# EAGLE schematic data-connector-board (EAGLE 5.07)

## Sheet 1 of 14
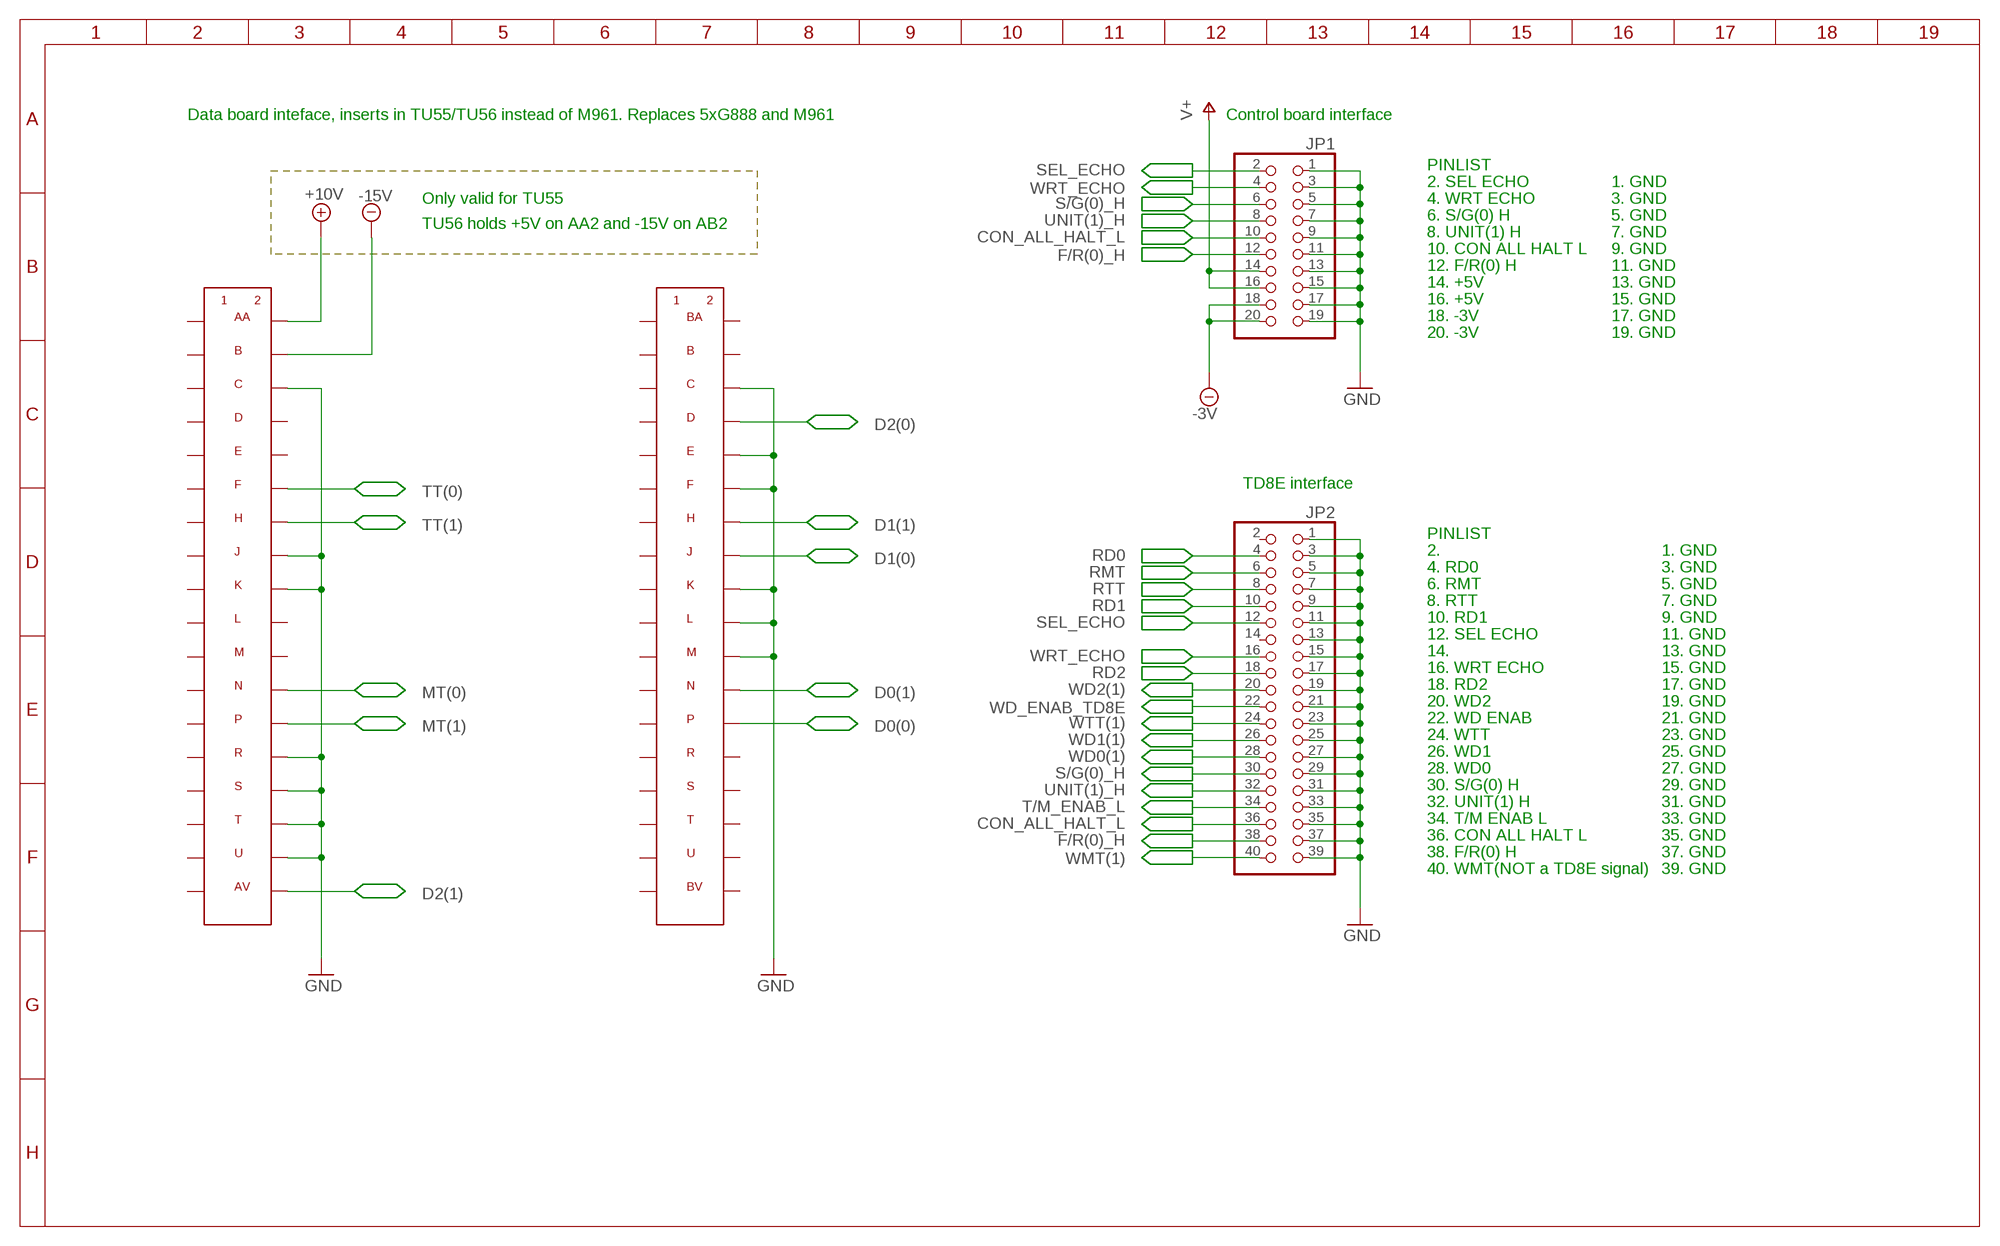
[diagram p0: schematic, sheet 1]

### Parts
J1  FLIPCHIP_2  FLIPCHIP_2-SBSOPEN  [FLIPCHIP-2-OPEN]
JP1  PINHD-2X10/90-FRAMED  [2Z10/90-FRAMED]
JP2  PINHD-2X20/90-FRAMED  [2X20/90-FRAMED]

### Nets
+10V: J1.AA2 ; also sheet 13
-3V: JP1.18 JP1.20 ; also sheet 13,14
-15V: J1.AB2 ; also sheet 13
CON_ALL_HALT_L: JP1.10 JP2.36
D0(0): J1.BP2 ; also sheet 4,9
D0(1): J1.BN2 ; also sheet 4,9
D1(0): J1.BJ2 ; also sheet 5,10
D1(1): J1.BH2 ; also sheet 5,10
D2(0): J1.BD2 ; also sheet 6,11
D2(1): J1.AV2 ; also sheet 6,11
F/R(0)_H: JP1.12 JP2.38
GND: J1.AC2 J1.AJ2 J1.AK2 J1.AR2 J1.AS2 J1.AT2 J1.AU2 J1.BC2 J1.BE2 J1.BF2 J1.BK2 J1.BL2 J1.BM2 JP1.1 JP1.3 JP1.5 JP1.7 JP1.9 JP1.11 JP1.13 JP1.15 JP1.17 JP1.19 JP2.1 JP2.3 JP2.5 JP2.7 JP2.9 JP2.11 JP2.13 JP2.15 JP2.17 JP2.19 JP2.21 JP2.23 JP2.25 JP2.27 JP2.29 JP2.31 JP2.33 JP2.35 JP2.37 JP2.39 ; also sheet 2,3,4,5,6,7,8,9,10,11,12,13
MT(0): J1.AN2 ; also sheet 3,8
MT(1): J1.AP2 ; also sheet 3,8
RD0: JP2.4 ; also sheet 4,14
RD1: JP2.10 ; also sheet 5,14
RD2: JP2.18 ; also sheet 6,14
RMT: JP2.6 ; also sheet 3,14
RTT: JP2.8 ; also sheet 2,14
S/G(0)_H: JP1.6 JP2.30
SEL_ECHO: JP1.2 JP2.12
T/M_ENAB_L: JP2.34 ; also sheet 12
TT(0): J1.AF2 ; also sheet 2,7
TT(1): J1.AH2 ; also sheet 2,7
UNIT(1)_H: JP1.8 JP2.32
V+: JP1.14 JP1.16 ; also sheet 2,3,4,5,6,7,8,9,10,11,12,13,14
WD0(1): JP2.28 ; also sheet 8,9
WD1(1): JP2.26 ; also sheet 10
WD2(1): JP2.20 ; also sheet 11
WD_ENAB_TD8E: JP2.22 ; also sheet 12
WMT(1): JP2.40 ; also sheet 8
WRT_ECHO: JP1.4 JP2.16
WTT(1): JP2.24 ; also sheet 7
Unconnected: J1.AA1 J1.AB1 J1.AC1 J1.AD1 J1.AD2 J1.AE1 J1.AE2 J1.AF1 J1.AH1 J1.AJ1 J1.AK1 J1.AL1 J1.AL2 J1.AM1 J1.AM2 J1.AN1 J1.AP1 J1.AR1 J1.AS1 J1.AT1 J1.AU1 J1.AV1 J1.BA1 J1.BA2 J1.BB1 J1.BB2 J1.BC1 J1.BD1 J1.BE1 J1.BF1 J1.BH1 J1.BJ1 J1.BK1 J1.BL1 J1.BM1 J1.BN1 J1.BP1 J1.BR1 J1.BR2 J1.BS1 J1.BS2 J1.BT1 J1.BT2 J1.BU1 J1.BU2 J1.BV1 J1.BV2 JP2.2 JP2.14

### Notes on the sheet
- Data board inteface, inserts in TU55/TU56 instead of M961. Replaces 5xG888 and M961 | Control board interface
- PINLIST
- 2. SEL ECHO | 1. GND
- Only valid for TU55 | 4. WRT ECHO | 3. GND
- 6. S/G(0) H | 5. GND
- TU56 holds +5V on AA2 and -15V on AB2
- 8. UNIT(1) H | 7. GND
- 10. CON ALL HALT L | 9. GND
- 12. F/R(0) H | 11. GND
- 14. +5V | 13. GND
- 16. +5V | 15. GND
- 18. -3V | 17. GND
- 20. -3V | 19. GND
- TD8E interface
- PINLIST
- 2. | 1. GND
- 4. RD0 | 3. GND
- 6. RMT | 5. GND
- 8. RTT | 7. GND
- 10. RD1 | 9. GND
- 12. SEL ECHO | 11. GND
- 14. | 13. GND
- 16. WRT ECHO | 15. GND
- 18. RD2 | 17. GND
- 20. WD2 | 19. GND
- 22. WD ENAB | 21. GND
- 24. WTT | 23. GND
- 26. WD1 | 25. GND
- 28. WD0 | 27. GND
- 30. S/G(0) H | 29. GND
- 32. UNIT(1) H | 31. GND
- 34. T/M ENAB L | 33. GND
- 36. CON ALL HALT L | 35. GND
- 38. F/R(0) H | 37. GND
- 40. WMT(NOT a TD8E signal) | 39. GND

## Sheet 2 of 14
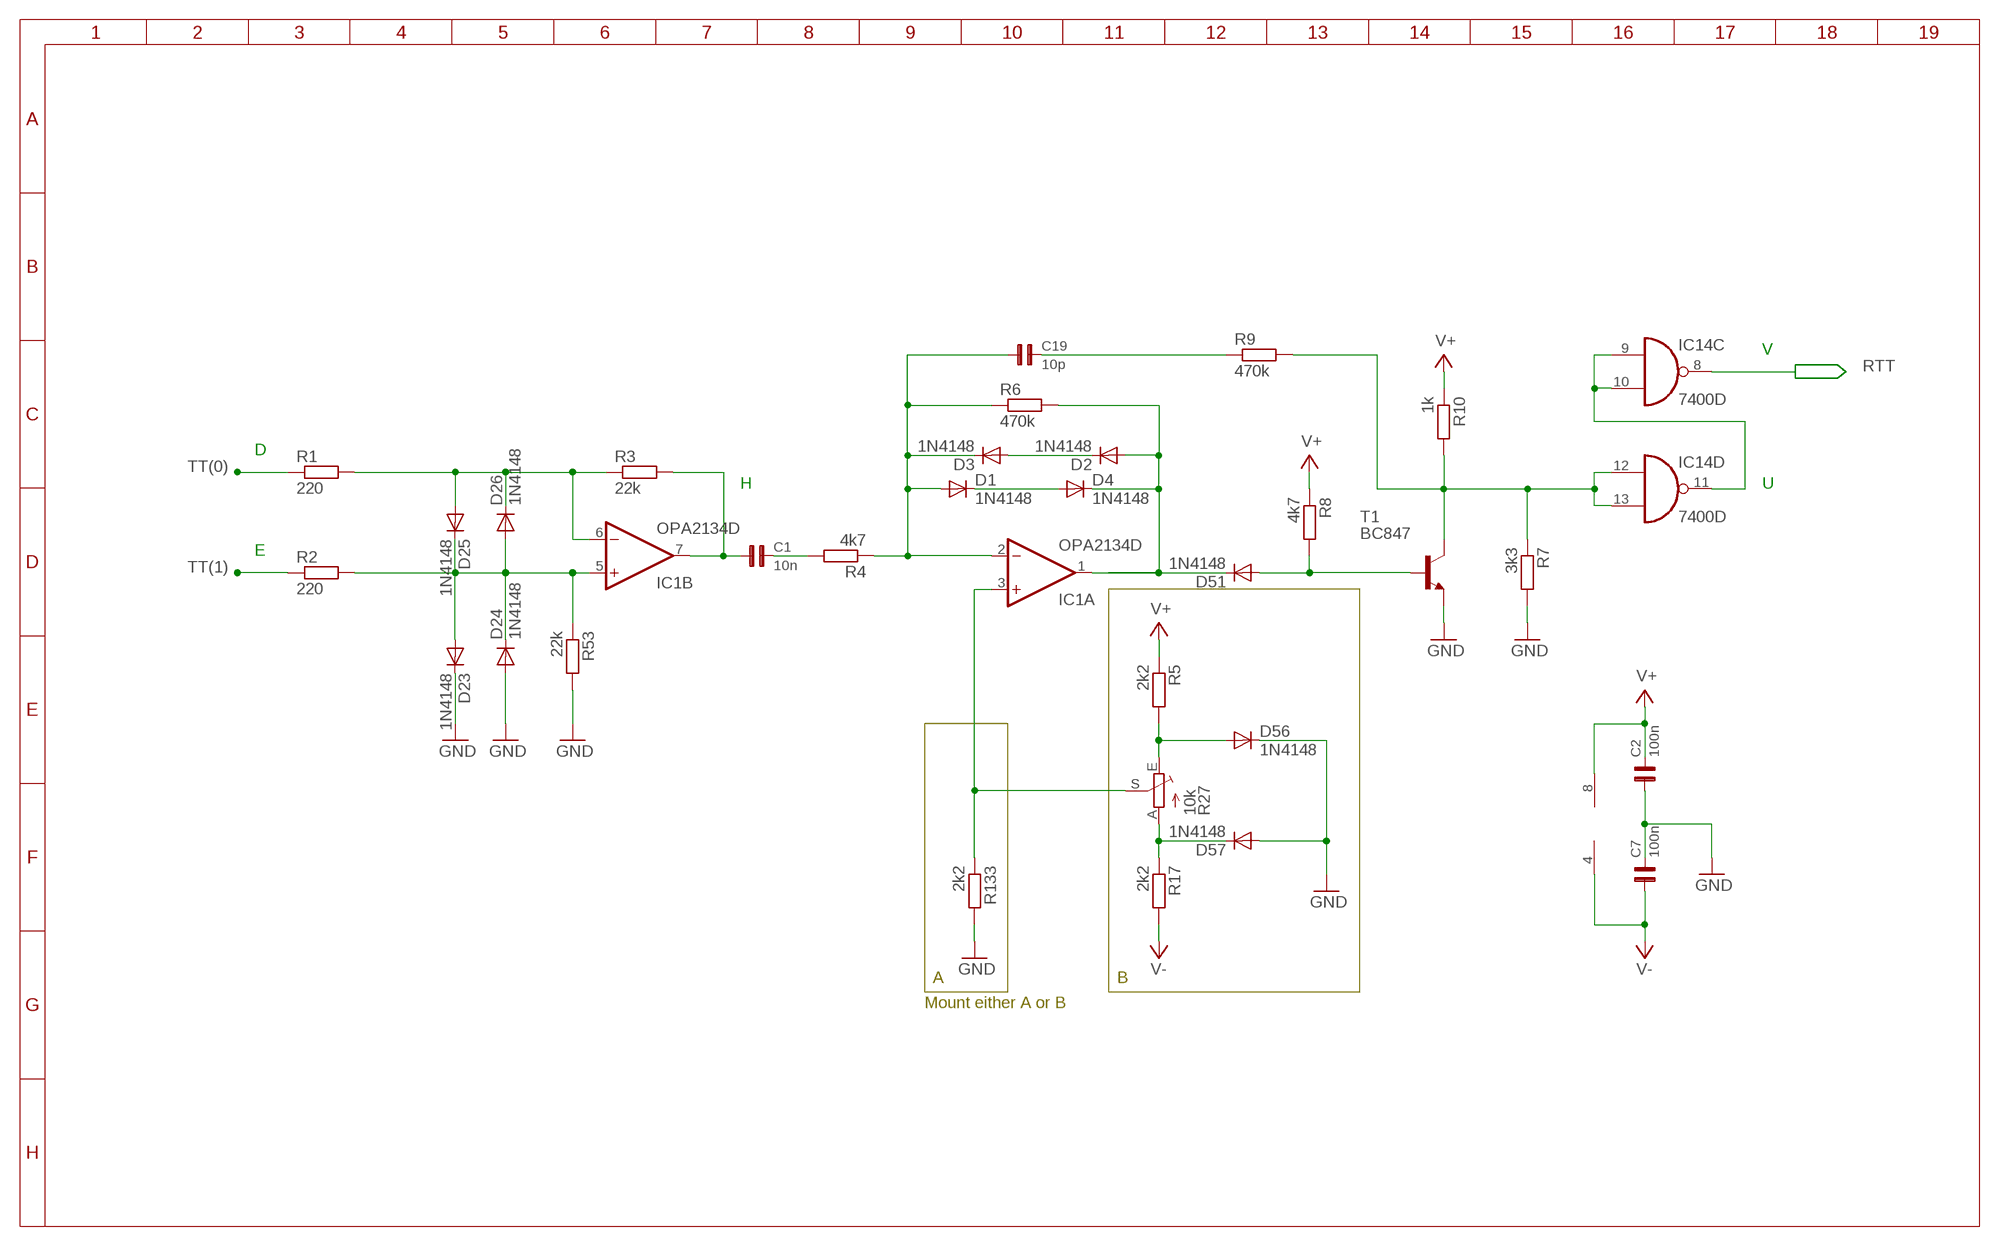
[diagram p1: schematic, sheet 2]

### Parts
C1  10n  C0805  [0805]
C2  100n  C0805  [0805]
C7  100n  C0805  [0805]
C19  10p  C0805  [0805]
D1  1N4148  1N4148-Y  [SOD123]
D2  1N4148  1N4148-Y  [SOD123]
D3  1N4148  1N4148-Y  [SOD123]
D4  1N4148  1N4148-Y  [SOD123]
D23  1N4148  1N4148-Y  [SOD123]
D24  1N4148  1N4148-Y  [SOD123]
D25  1N4148  1N4148-Y  [SOD123]
D26  1N4148  1N4148-Y  [SOD123]
D51  1N4148  1N4148-Y  [SOD123]
D56  1N4148  1N4148-Y  [SOD123]
D57  1N4148  1N4148-Y  [SOD123]
IC1  OPA2134D  [SOIC8]
IC14  7400D  [SO14]
R1  220  R-EU_R0805  [R0805]
R2  220  R-EU_R0805  [R0805]
R3  22k  R-EU_R0805  [R0805]
R4  4k7  R-EU_R0805  [R0805]
R5  2k2  R-EU_R0805  [R0805]
R6  470k  R-EU_R0805  [R0805]
R7  3k3  R-EU_R0805  [R0805]
R8  4k7  R-EU_R0805  [R0805]
R9  470k  R-EU_R0805  [R0805]
R10  1k  R-EU_R0805  [R0805]
R17  2k2  R-EU_R0805  [R0805]
R27  10k  TRIM_EU-SP19L  [SP19L]
R53  22k  R-EU_R0805  [R0805]
R133  2k2  R-EU_R0805  [R0805]
T1  BC847  [SOT23]

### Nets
GND: C2.1 C7.2 D23.C D24.A D56.C D57.A R7.2 R53.2 R133.2 T1.2(E) ; also sheet 1,3,4,5,6,7,8,9,10,11,12,13
N$1: D25.A D26.C IC1.6(B:-IN) R1.2 R3.1
N$3: C1.1 IC1.7(B:OUT) R3.2
N$4: D1.C D4.A
N$5: C19.1 D1.A D3.C IC1.2(A:-IN) R4.1 R6.1
N$7: D2.A D4.C D51.C IC1.1(A:OUT) R6.2
N$8: D51.A R8.2 T1.1(B)
N$9: C19.2 R9.1
N$11: D2.C D3.A
N$12: C1.2 R4.2
N$33: IC1.3(A:+IN) R27.S R133.1
N$47: D56.A R5.2 R27.E
N$73: D57.C R17.1 R27.A
N$116: IC14.9(C:I0) IC14.10(C:I1) IC14.11(D:O)
N$128: D23.A D24.C D25.C D26.A IC1.5(B:+IN) R2.2 R53.1
RTT: IC14.8(C:O) ; also sheet 1,14
TIMING: IC14.12(D:I0) IC14.13(D:I1) R7.1 R9.2 R10.2 T1.3(C)
TT(0): R1.1 ; also sheet 1,7
TT(1): R2.1 ; also sheet 1,7
V+: C2.2 IC1.8(P:V+) R5.1 R8.1 R10.1 ; also sheet 1,3,4,5,6,7,8,9,10,11,12,13,14
V-: C7.1 IC1.4(P:V-) R17.2 ; also sheet 3,4,5,6,13,14

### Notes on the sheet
- V
- D
- H | U
- E
- A | B
- Mount either A or B

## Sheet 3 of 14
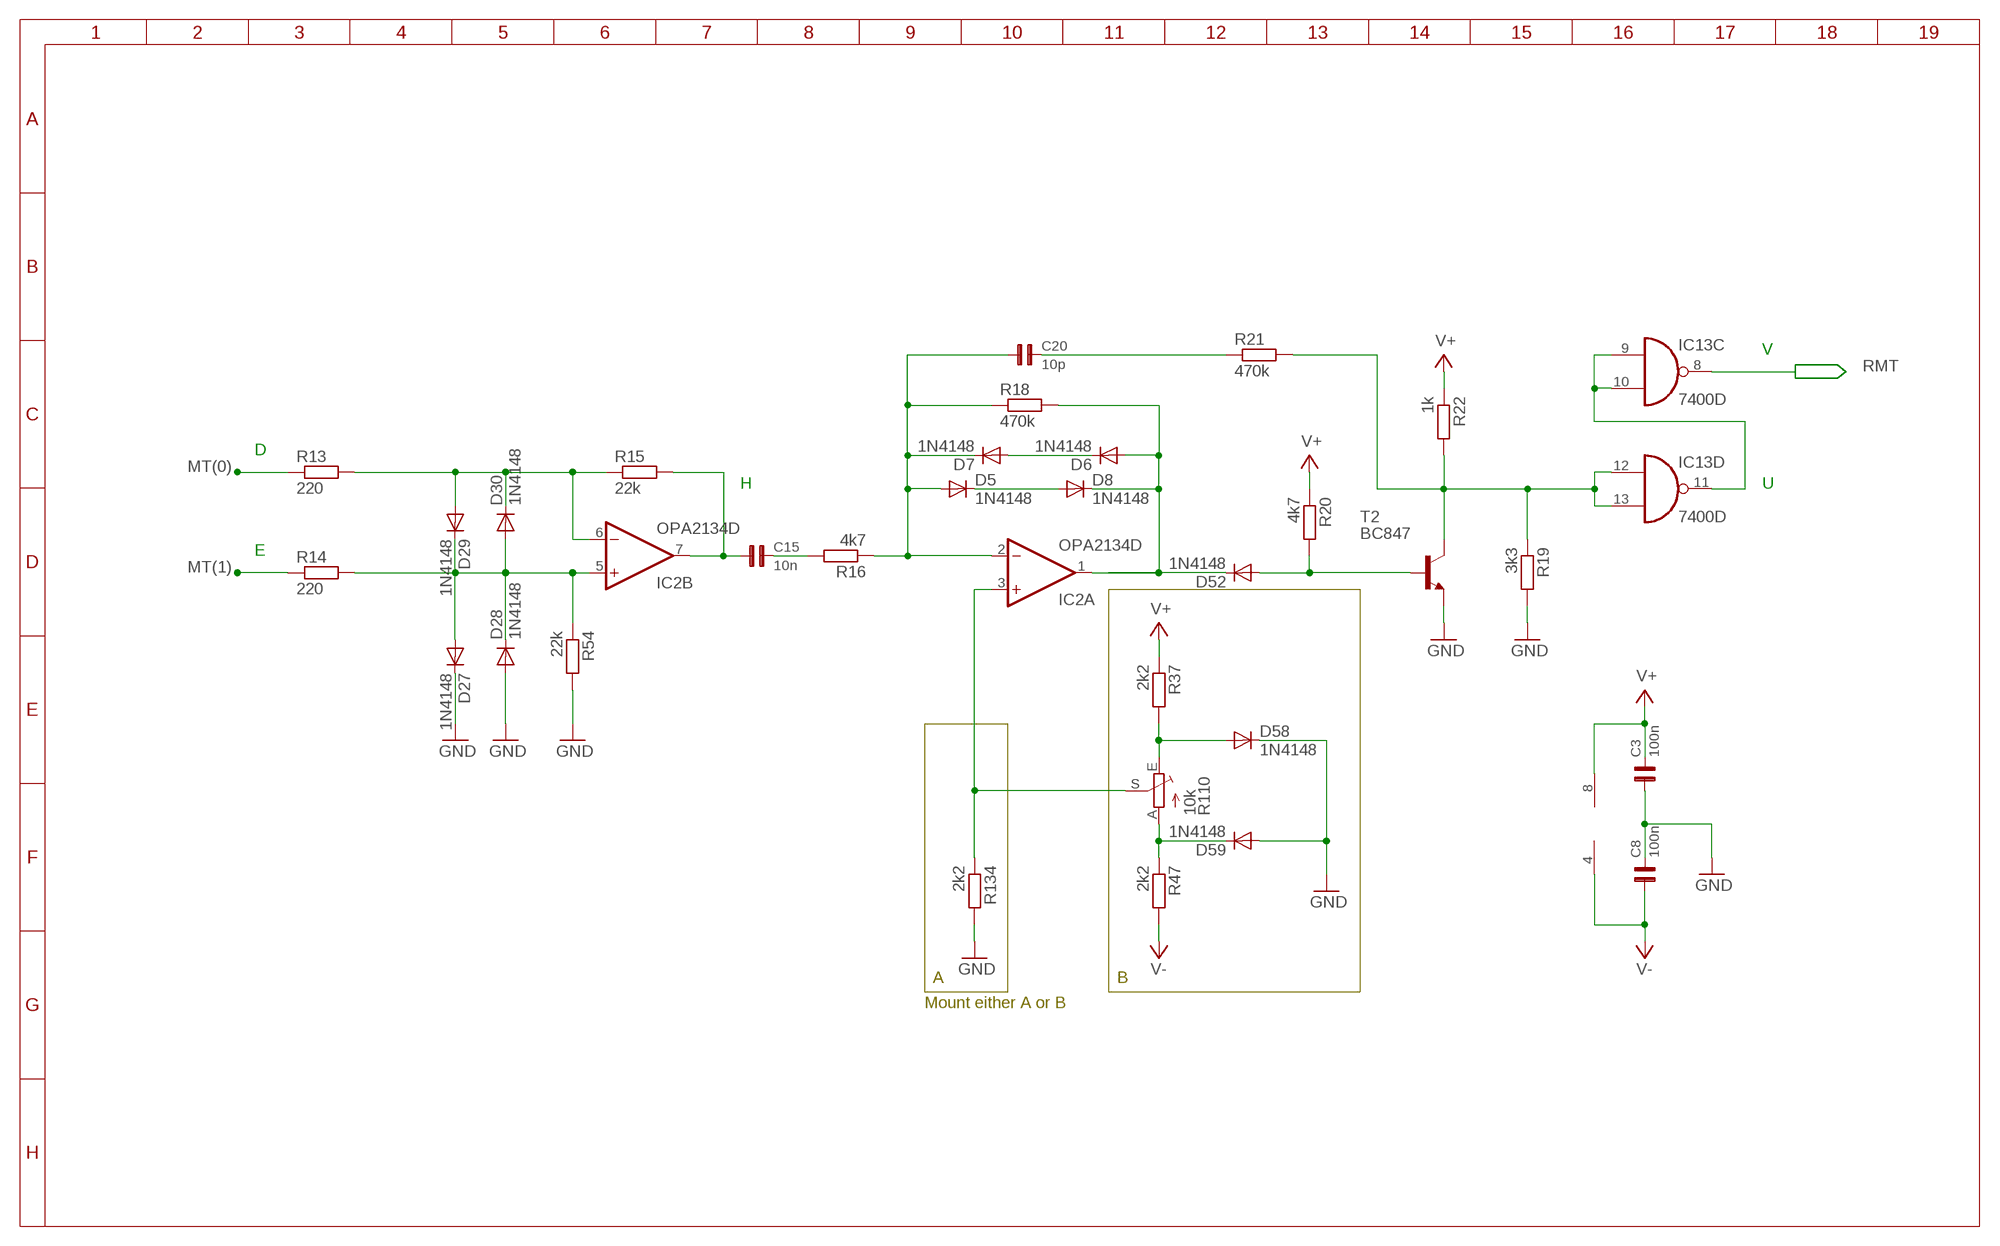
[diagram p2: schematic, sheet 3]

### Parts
C3  100n  C0805  [0805]
C8  100n  C0805  [0805]
C15  10n  C0805  [0805]
C20  10p  C0805  [0805]
D5  1N4148  1N4148-Y  [SOD123]
D6  1N4148  1N4148-Y  [SOD123]
D7  1N4148  1N4148-Y  [SOD123]
D8  1N4148  1N4148-Y  [SOD123]
D27  1N4148  1N4148-Y  [SOD123]
D28  1N4148  1N4148-Y  [SOD123]
D29  1N4148  1N4148-Y  [SOD123]
D30  1N4148  1N4148-Y  [SOD123]
D52  1N4148  1N4148-Y  [SOD123]
D58  1N4148  1N4148-Y  [SOD123]
D59  1N4148  1N4148-Y  [SOD123]
IC2  OPA2134D  [SOIC8]
IC13  7400D  [SO14]
R13  220  R-EU_R0805  [R0805]
R14  220  R-EU_R0805  [R0805]
R15  22k  R-EU_R0805  [R0805]
R16  4k7  R-EU_R0805  [R0805]
R18  470k  R-EU_R0805  [R0805]
R19  3k3  R-EU_R0805  [R0805]
R20  4k7  R-EU_R0805  [R0805]
R21  470k  R-EU_R0805  [R0805]
R22  1k  R-EU_R0805  [R0805]
R37  2k2  R-EU_R0805  [R0805]
R47  2k2  R-EU_R0805  [R0805]
R54  22k  R-EU_R0805  [R0805]
R110  10k  TRIM_EU-SP19L  [SP19L]
R134  2k2  R-EU_R0805  [R0805]
T2  BC847  [SOT23]

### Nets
GND: C3.1 C8.2 D27.C D28.A D58.C D59.A R19.2 R54.2 R134.2 T2.2(E) ; also sheet 1,2,4,5,6,7,8,9,10,11,12,13
MARK: IC13.12(D:I0) IC13.13(D:I1) R19.1 R21.2 R22.2 T2.3(C)
MT(0): R13.1 ; also sheet 1,8
MT(1): R14.1 ; also sheet 1,8
N$27: C15.1 IC2.7(B:OUT) R15.2
N$28: D5.C D8.A
N$29: C20.1 D5.A D7.C IC2.2(A:-IN) R16.1 R18.1
N$30: D6.A D8.C D52.C IC2.1(A:OUT) R18.2
N$32: D52.A R20.2 T2.1(B)
N$35: C15.2 R16.2
N$38: D6.C D7.A
N$49: IC2.3(A:+IN) R110.S R134.1
N$76: IC13.9(C:I0) IC13.10(C:I1) IC13.11(D:O)
N$84: C20.2 R21.1
N$86: D58.A R37.2 R110.E
N$87: D59.C R47.1 R110.A
N$129: D29.A D30.C IC2.6(B:-IN) R13.2 R15.1
N$130: D27.A D28.C D29.C D30.A IC2.5(B:+IN) R14.2 R54.1
RMT: IC13.8(C:O) ; also sheet 1,14
V+: C3.2 IC2.8(P:V+) R20.1 R22.1 R37.1 ; also sheet 1,2,4,5,6,7,8,9,10,11,12,13,14
V-: C8.1 IC2.4(P:V-) R47.2 ; also sheet 2,4,5,6,13,14

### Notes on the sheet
- V
- D
- H | U
- E
- A | B
- Mount either A or B

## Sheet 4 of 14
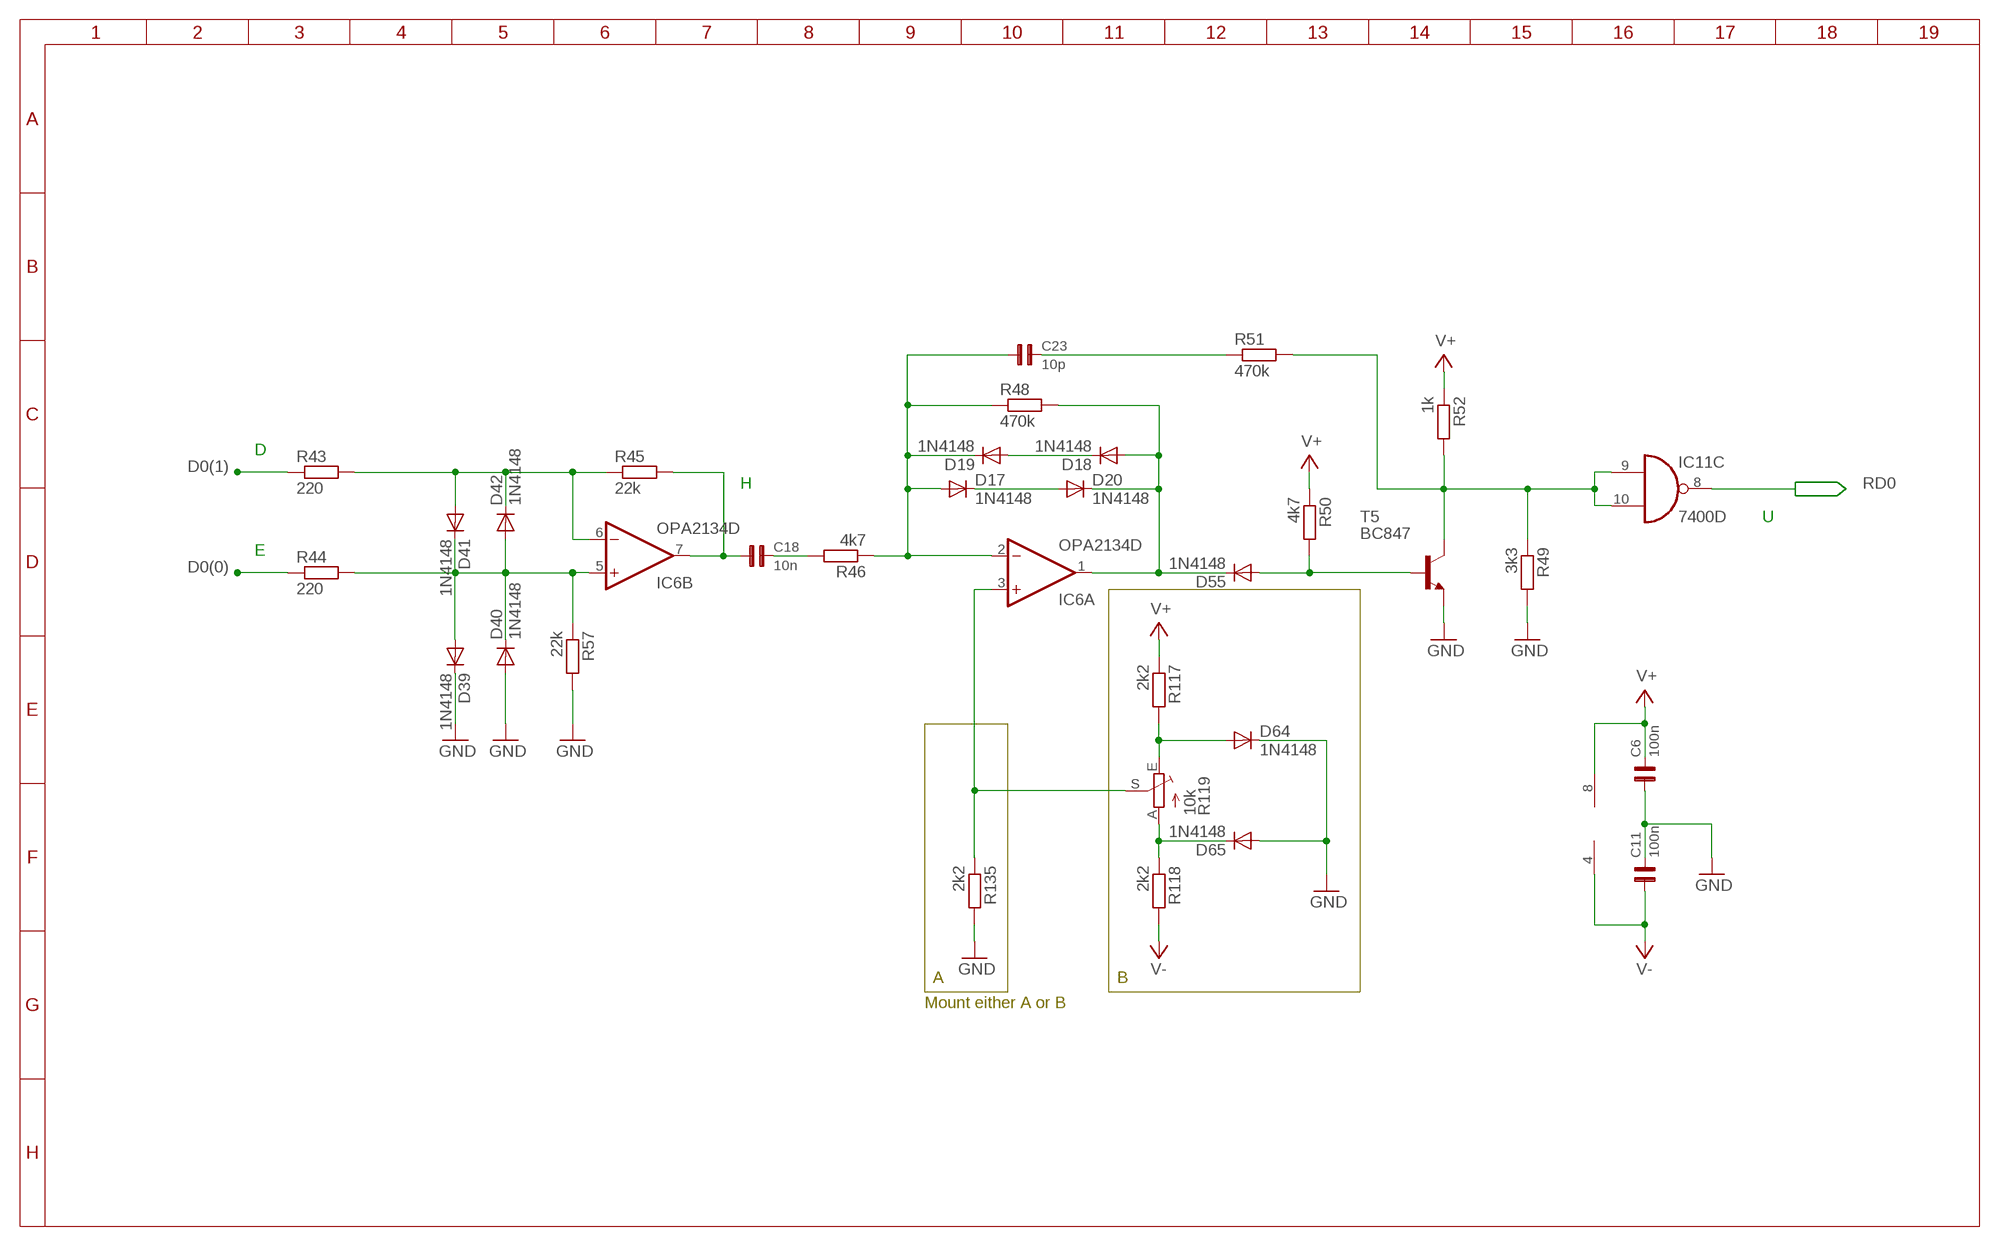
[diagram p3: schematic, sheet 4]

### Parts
C6  100n  C0805  [0805]
C11  100n  C0805  [0805]
C18  10n  C0805  [0805]
C23  10p  C0805  [0805]
D17  1N4148  1N4148-Y  [SOD123]
D18  1N4148  1N4148-Y  [SOD123]
D19  1N4148  1N4148-Y  [SOD123]
D20  1N4148  1N4148-Y  [SOD123]
D39  1N4148  1N4148-Y  [SOD123]
D40  1N4148  1N4148-Y  [SOD123]
D41  1N4148  1N4148-Y  [SOD123]
D42  1N4148  1N4148-Y  [SOD123]
D55  1N4148  1N4148-Y  [SOD123]
D64  1N4148  1N4148-Y  [SOD123]
D65  1N4148  1N4148-Y  [SOD123]
IC6  OPA2134D  [SOIC8]
IC11  7400D  [SO14]
R43  220  R-EU_R0805  [R0805]
R44  220  R-EU_R0805  [R0805]
R45  22k  R-EU_R0805  [R0805]
R46  4k7  R-EU_R0805  [R0805]
R48  470k  R-EU_R0805  [R0805]
R49  3k3  R-EU_R0805  [R0805]
R50  4k7  R-EU_R0805  [R0805]
R51  470k  R-EU_R0805  [R0805]
R52  1k  R-EU_R0805  [R0805]
R57  22k  R-EU_R0805  [R0805]
R117  2k2  R-EU_R0805  [R0805]
R118  2k2  R-EU_R0805  [R0805]
R119  10k  TRIM_EU-SP19L  [SP19L]
R135  2k2  R-EU_R0805  [R0805]
T5  BC847  [SOT23]

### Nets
D0(0): R44.1 ; also sheet 1,9
D0(1): R43.1 ; also sheet 1,9
DATA1: IC11.9(C:I0) IC11.10(C:I1) R49.1 R51.2 R52.2 T5.3(C)
GND: C6.1 C11.2 D39.C D40.A D64.C D65.A R49.2 R57.2 R135.2 T5.2(E) ; also sheet 1,2,3,5,6,7,8,9,10,11,12,13
N$10: C23.2 R51.1
N$66: C18.1 IC6.7(B:OUT) R45.2
N$67: D17.C D20.A
N$68: C23.1 D17.A D19.C IC6.2(A:-IN) R46.1 R48.1
N$69: D18.A D20.C D55.C IC6.1(A:OUT) R48.2
N$71: D55.A R50.2 T5.1(B)
N$74: C18.2 R46.2
N$77: D18.C D19.A
N$79: IC6.3(A:+IN) R119.S R135.1
N$92: D64.A R117.2 R119.E
N$93: D65.C R118.1 R119.A
N$141: D41.A D42.C IC6.6(B:-IN) R43.2 R45.1
N$142: D39.A D40.C D41.C D42.A IC6.5(B:+IN) R44.2 R57.1
RD0: IC11.8(C:O) ; also sheet 1,14
V+: C6.2 IC6.8(P:V+) R50.1 R52.1 R117.1 ; also sheet 1,2,3,5,6,7,8,9,10,11,12,13,14
V-: C11.1 IC6.4(P:V-) R118.2 ; also sheet 2,3,5,6,13,14

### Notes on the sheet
- D
- H
- U
- E
- A | B
- Mount either A or B

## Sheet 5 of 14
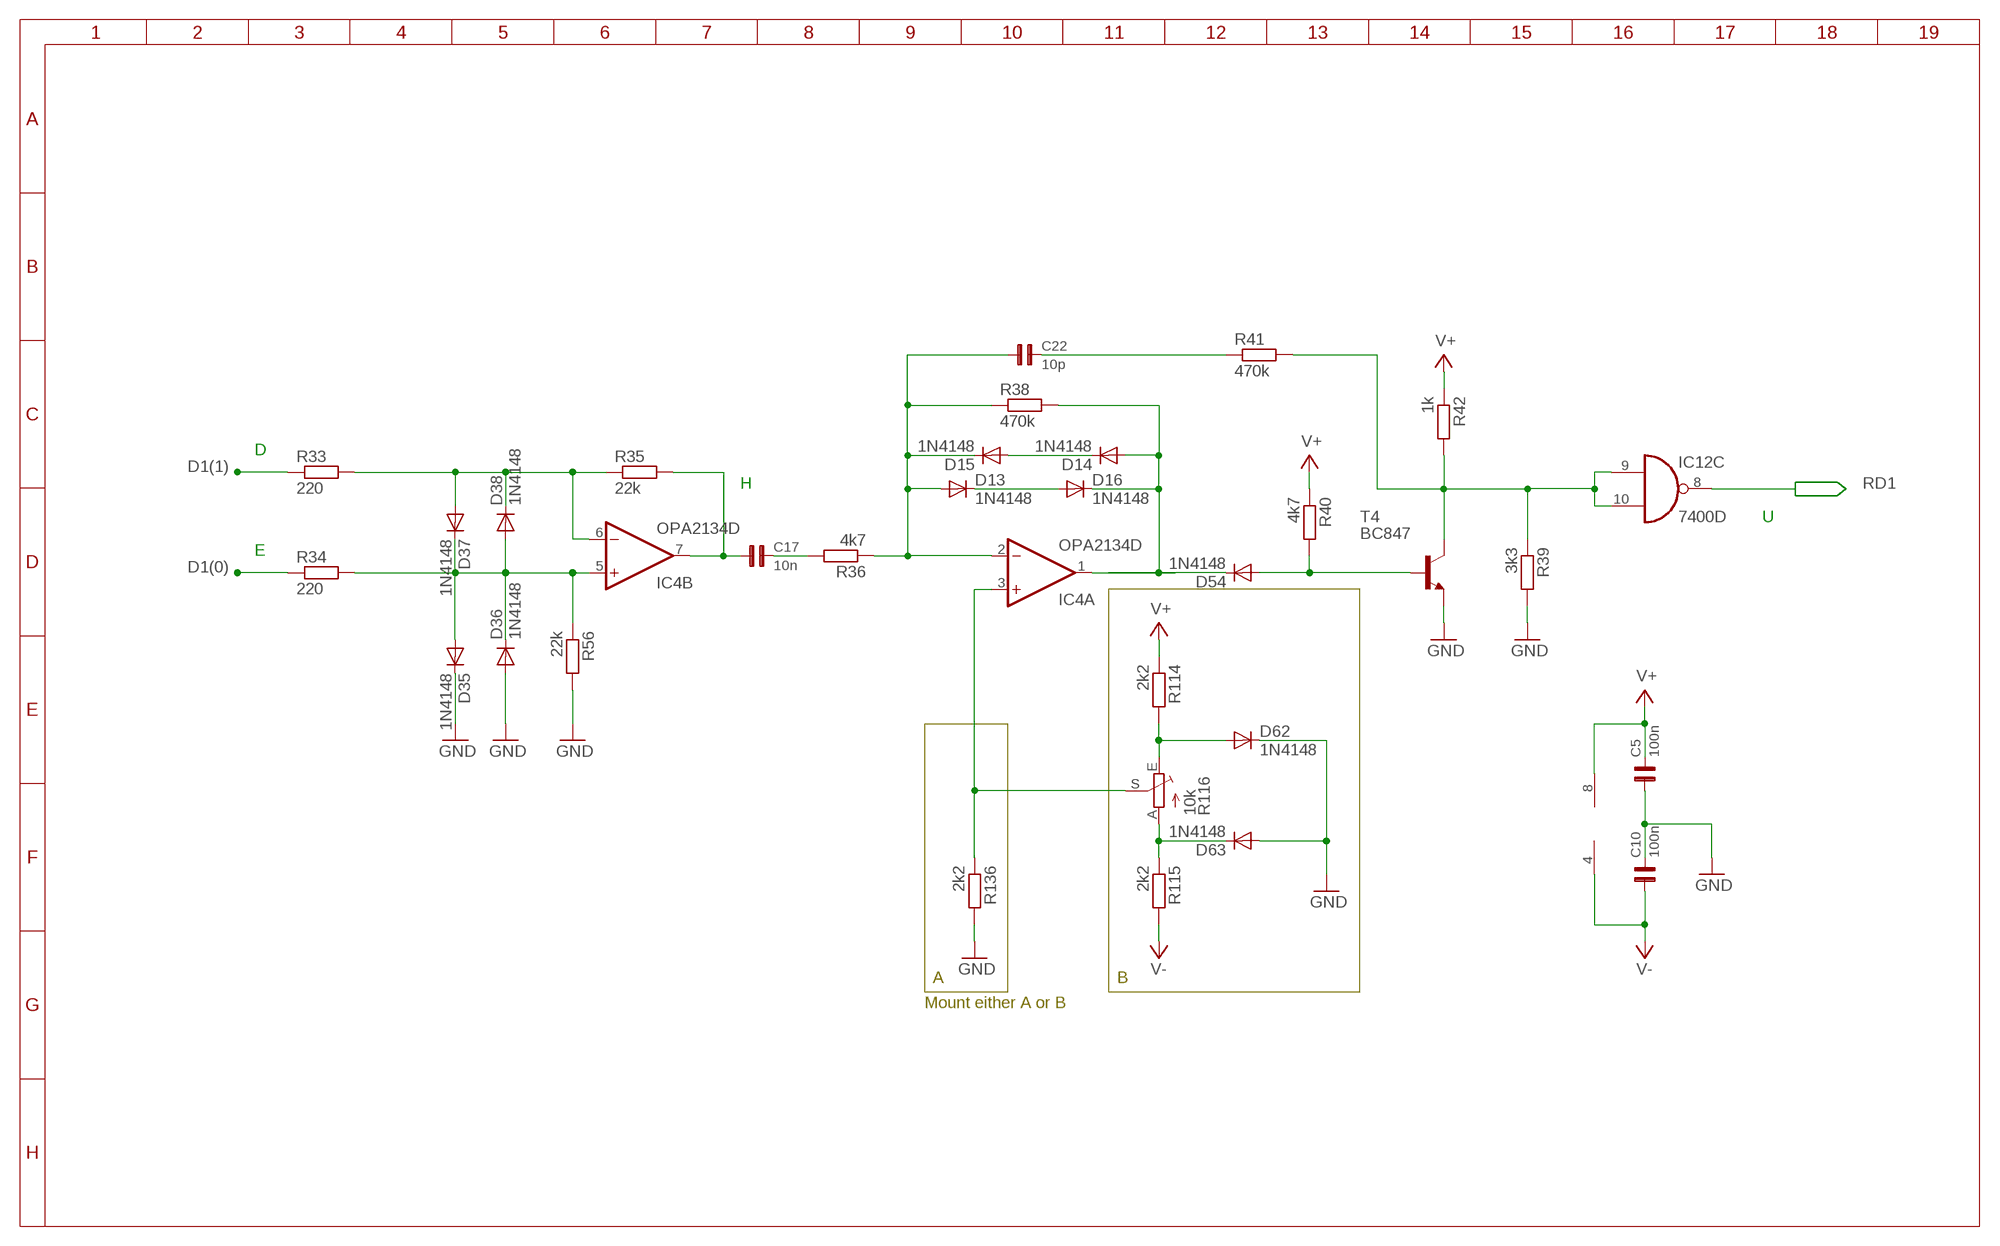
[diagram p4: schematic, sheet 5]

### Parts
C5  100n  C0805  [0805]
C10  100n  C0805  [0805]
C17  10n  C0805  [0805]
C22  10p  C0805  [0805]
D13  1N4148  1N4148-Y  [SOD123]
D14  1N4148  1N4148-Y  [SOD123]
D15  1N4148  1N4148-Y  [SOD123]
D16  1N4148  1N4148-Y  [SOD123]
D35  1N4148  1N4148-Y  [SOD123]
D36  1N4148  1N4148-Y  [SOD123]
D37  1N4148  1N4148-Y  [SOD123]
D38  1N4148  1N4148-Y  [SOD123]
D54  1N4148  1N4148-Y  [SOD123]
D62  1N4148  1N4148-Y  [SOD123]
D63  1N4148  1N4148-Y  [SOD123]
IC4  OPA2134D  [SOIC8]
IC12  7400D  [SO14]
R33  220  R-EU_R0805  [R0805]
R34  220  R-EU_R0805  [R0805]
R35  22k  R-EU_R0805  [R0805]
R36  4k7  R-EU_R0805  [R0805]
R38  470k  R-EU_R0805  [R0805]
R39  3k3  R-EU_R0805  [R0805]
R40  4k7  R-EU_R0805  [R0805]
R41  470k  R-EU_R0805  [R0805]
R42  1k  R-EU_R0805  [R0805]
R56  22k  R-EU_R0805  [R0805]
R114  2k2  R-EU_R0805  [R0805]
R115  2k2  R-EU_R0805  [R0805]
R116  10k  TRIM_EU-SP19L  [SP19L]
R136  2k2  R-EU_R0805  [R0805]
T4  BC847  [SOT23]

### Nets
D1(0): R34.1 ; also sheet 1,10
D1(1): R33.1 ; also sheet 1,10
DATA2: IC12.9(C:I0) IC12.10(C:I1) R39.1 R41.2 R42.2 T4.3(C)
GND: C5.1 C10.2 D35.C D36.A D62.C D63.A R39.2 R56.2 R136.2 T4.2(E) ; also sheet 1,2,3,4,6,7,8,9,10,11,12,13
N$34: C22.2 R41.1
N$53: C17.1 IC4.7(B:OUT) R35.2
N$54: D13.C D16.A
N$55: C22.1 D13.A D15.C IC4.2(A:-IN) R36.1 R38.1
N$56: D14.A D16.C D54.C IC4.1(A:OUT) R38.2
N$58: D54.A R40.2 T4.1(B)
N$61: C17.2 R36.2
N$64: D14.C D15.A
N$90: D62.A R114.2 R116.E
N$91: D63.C R115.1 R116.A
N$118: IC4.3(A:+IN) R116.S R136.1
N$137: D37.A D38.C IC4.6(B:-IN) R33.2 R35.1
N$138: D35.A D36.C D37.C D38.A IC4.5(B:+IN) R34.2 R56.1
RD1: IC12.8(C:O) ; also sheet 1,14
V+: C5.2 IC4.8(P:V+) R40.1 R42.1 R114.1 ; also sheet 1,2,3,4,6,7,8,9,10,11,12,13,14
V-: C10.1 IC4.4(P:V-) R115.2 ; also sheet 2,3,4,6,13,14

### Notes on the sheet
- D
- H
- U
- E
- A | B
- Mount either A or B

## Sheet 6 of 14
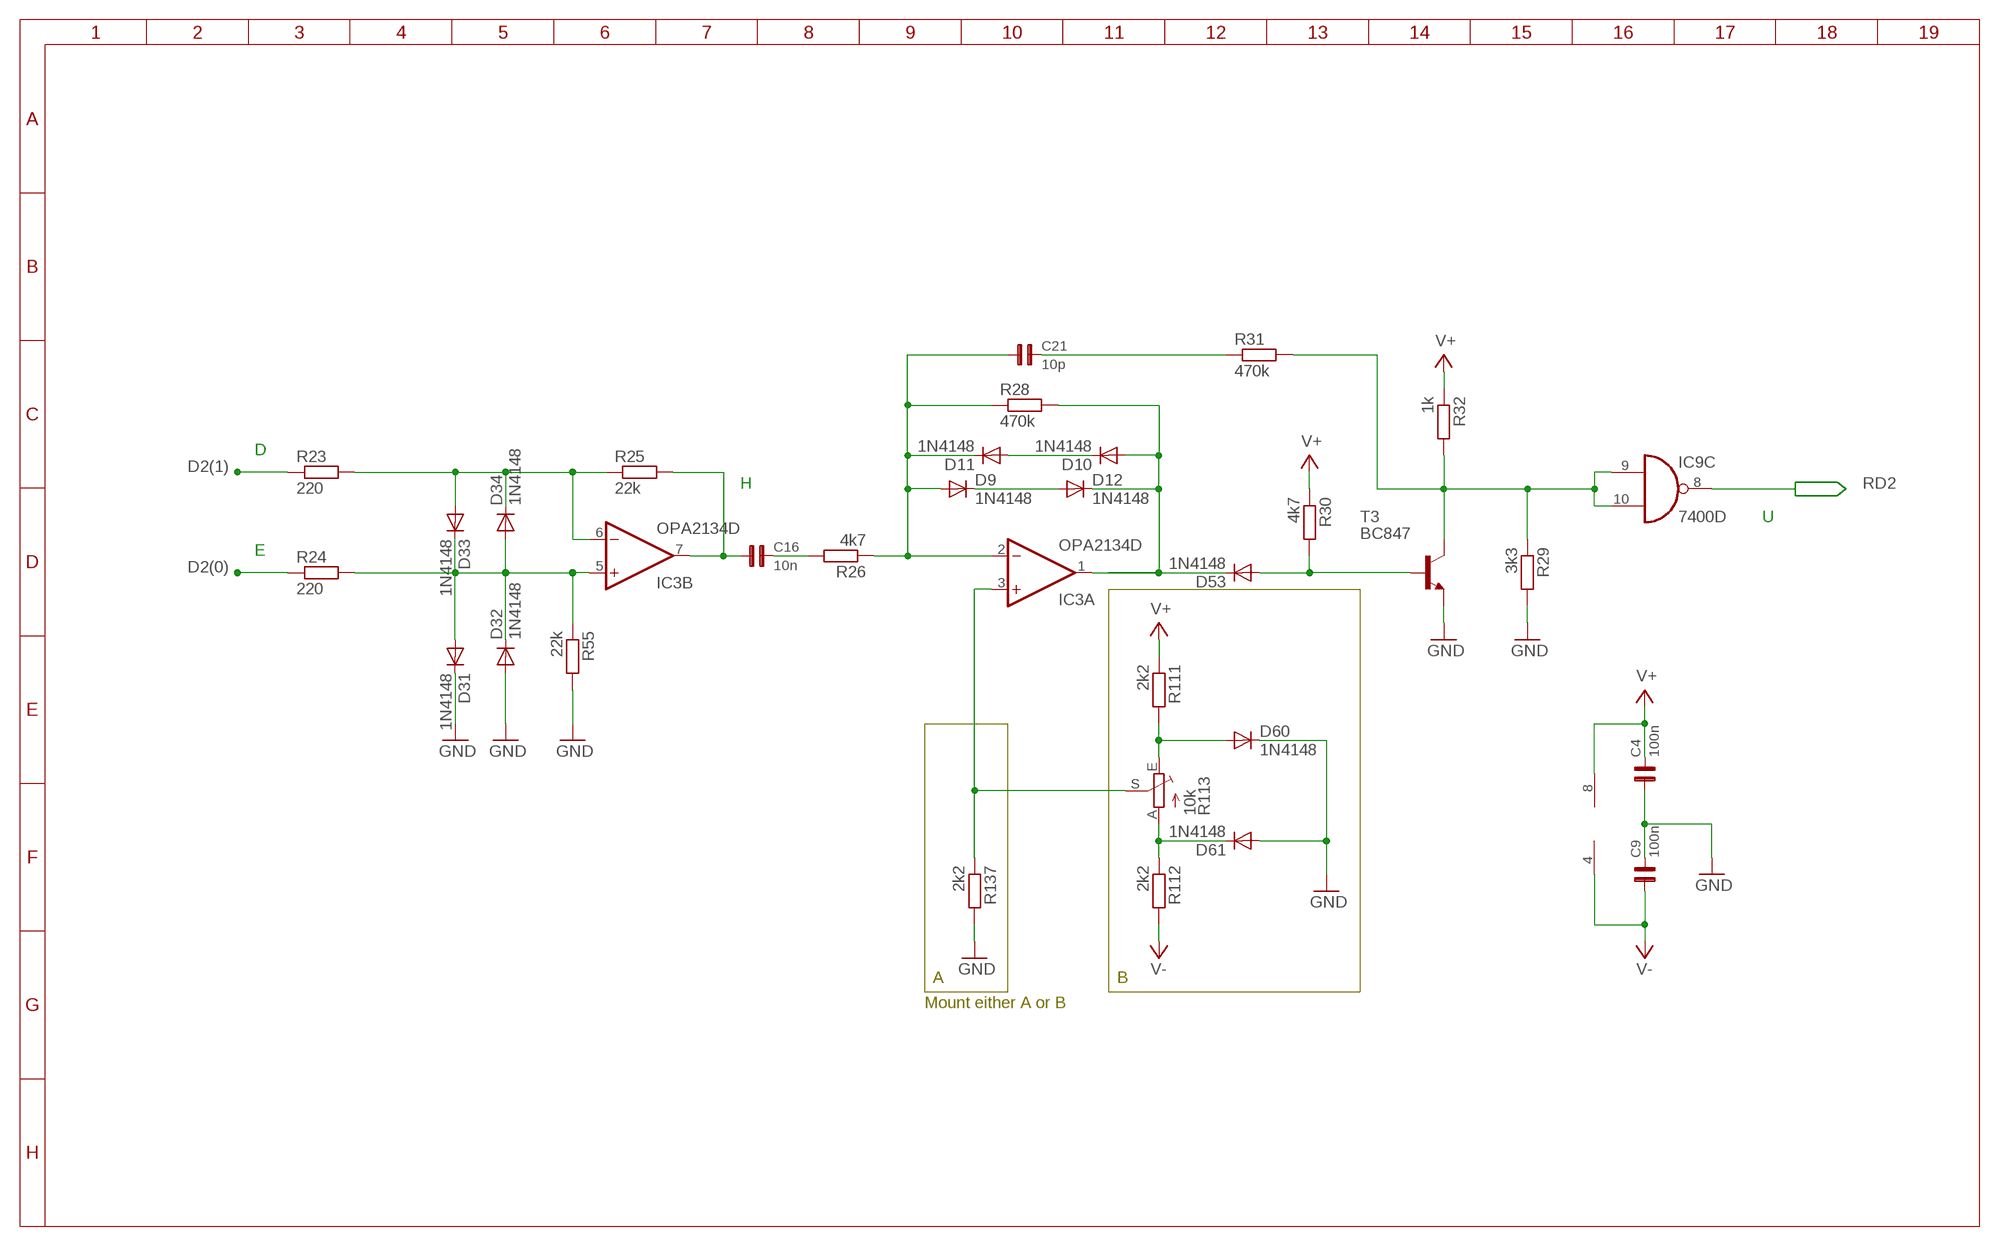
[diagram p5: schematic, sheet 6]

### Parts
C4  100n  C0805  [0805]
C9  100n  C0805  [0805]
C16  10n  C0805  [0805]
C21  10p  C0805  [0805]
D9  1N4148  1N4148-Y  [SOD123]
D10  1N4148  1N4148-Y  [SOD123]
D11  1N4148  1N4148-Y  [SOD123]
D12  1N4148  1N4148-Y  [SOD123]
D31  1N4148  1N4148-Y  [SOD123]
D32  1N4148  1N4148-Y  [SOD123]
D33  1N4148  1N4148-Y  [SOD123]
D34  1N4148  1N4148-Y  [SOD123]
D53  1N4148  1N4148-Y  [SOD123]
D60  1N4148  1N4148-Y  [SOD123]
D61  1N4148  1N4148-Y  [SOD123]
IC3  OPA2134D  [SOIC8]
IC9  7400D  [SO14]
R23  220  R-EU_R0805  [R0805]
R24  220  R-EU_R0805  [R0805]
R25  22k  R-EU_R0805  [R0805]
R26  4k7  R-EU_R0805  [R0805]
R28  470k  R-EU_R0805  [R0805]
R29  3k3  R-EU_R0805  [R0805]
R30  4k7  R-EU_R0805  [R0805]
R31  470k  R-EU_R0805  [R0805]
R32  1k  R-EU_R0805  [R0805]
R55  22k  R-EU_R0805  [R0805]
R111  2k2  R-EU_R0805  [R0805]
R112  2k2  R-EU_R0805  [R0805]
R113  10k  TRIM_EU-SP19L  [SP19L]
R137  2k2  R-EU_R0805  [R0805]
T3  BC847  [SOT23]

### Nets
D2(0): R24.1 ; also sheet 1,11
D2(1): R23.1 ; also sheet 1,11
DATA3: IC9.9(C:I0) IC9.10(C:I1) R29.1 R31.2 R32.2 T3.3(C)
GND: C4.1 C9.2 D31.C D32.A D60.C D61.A R29.2 R55.2 R137.2 T3.2(E) ; also sheet 1,2,3,4,5,7,8,9,10,11,12,13
N$40: C16.1 IC3.7(B:OUT) R25.2
N$41: D9.C D12.A
N$42: C21.1 D9.A D11.C IC3.2(A:-IN) R26.1 R28.1
N$43: D10.A D12.C D53.C IC3.1(A:OUT) R28.2
N$45: D53.A R30.2 T3.1(B)
N$48: C16.2 R26.2
N$51: D10.C D11.A
N$60: C21.2 R31.1
N$88: D60.A R111.2 R113.E
N$89: D61.C R112.1 R113.A
N$121: IC3.3(A:+IN) R113.S R137.1
N$133: D33.A D34.C IC3.6(B:-IN) R23.2 R25.1
N$134: D31.A D32.C D33.C D34.A IC3.5(B:+IN) R24.2 R55.1
RD2: IC9.8(C:O) ; also sheet 1,14
V+: C4.2 IC3.8(P:V+) R30.1 R32.1 R111.1 ; also sheet 1,2,3,4,5,7,8,9,10,11,12,13,14
V-: C9.1 IC3.4(P:V-) R112.2 ; also sheet 2,3,4,5,13,14

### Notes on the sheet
- D
- H
- U
- E
- A | B
- Mount either A or B

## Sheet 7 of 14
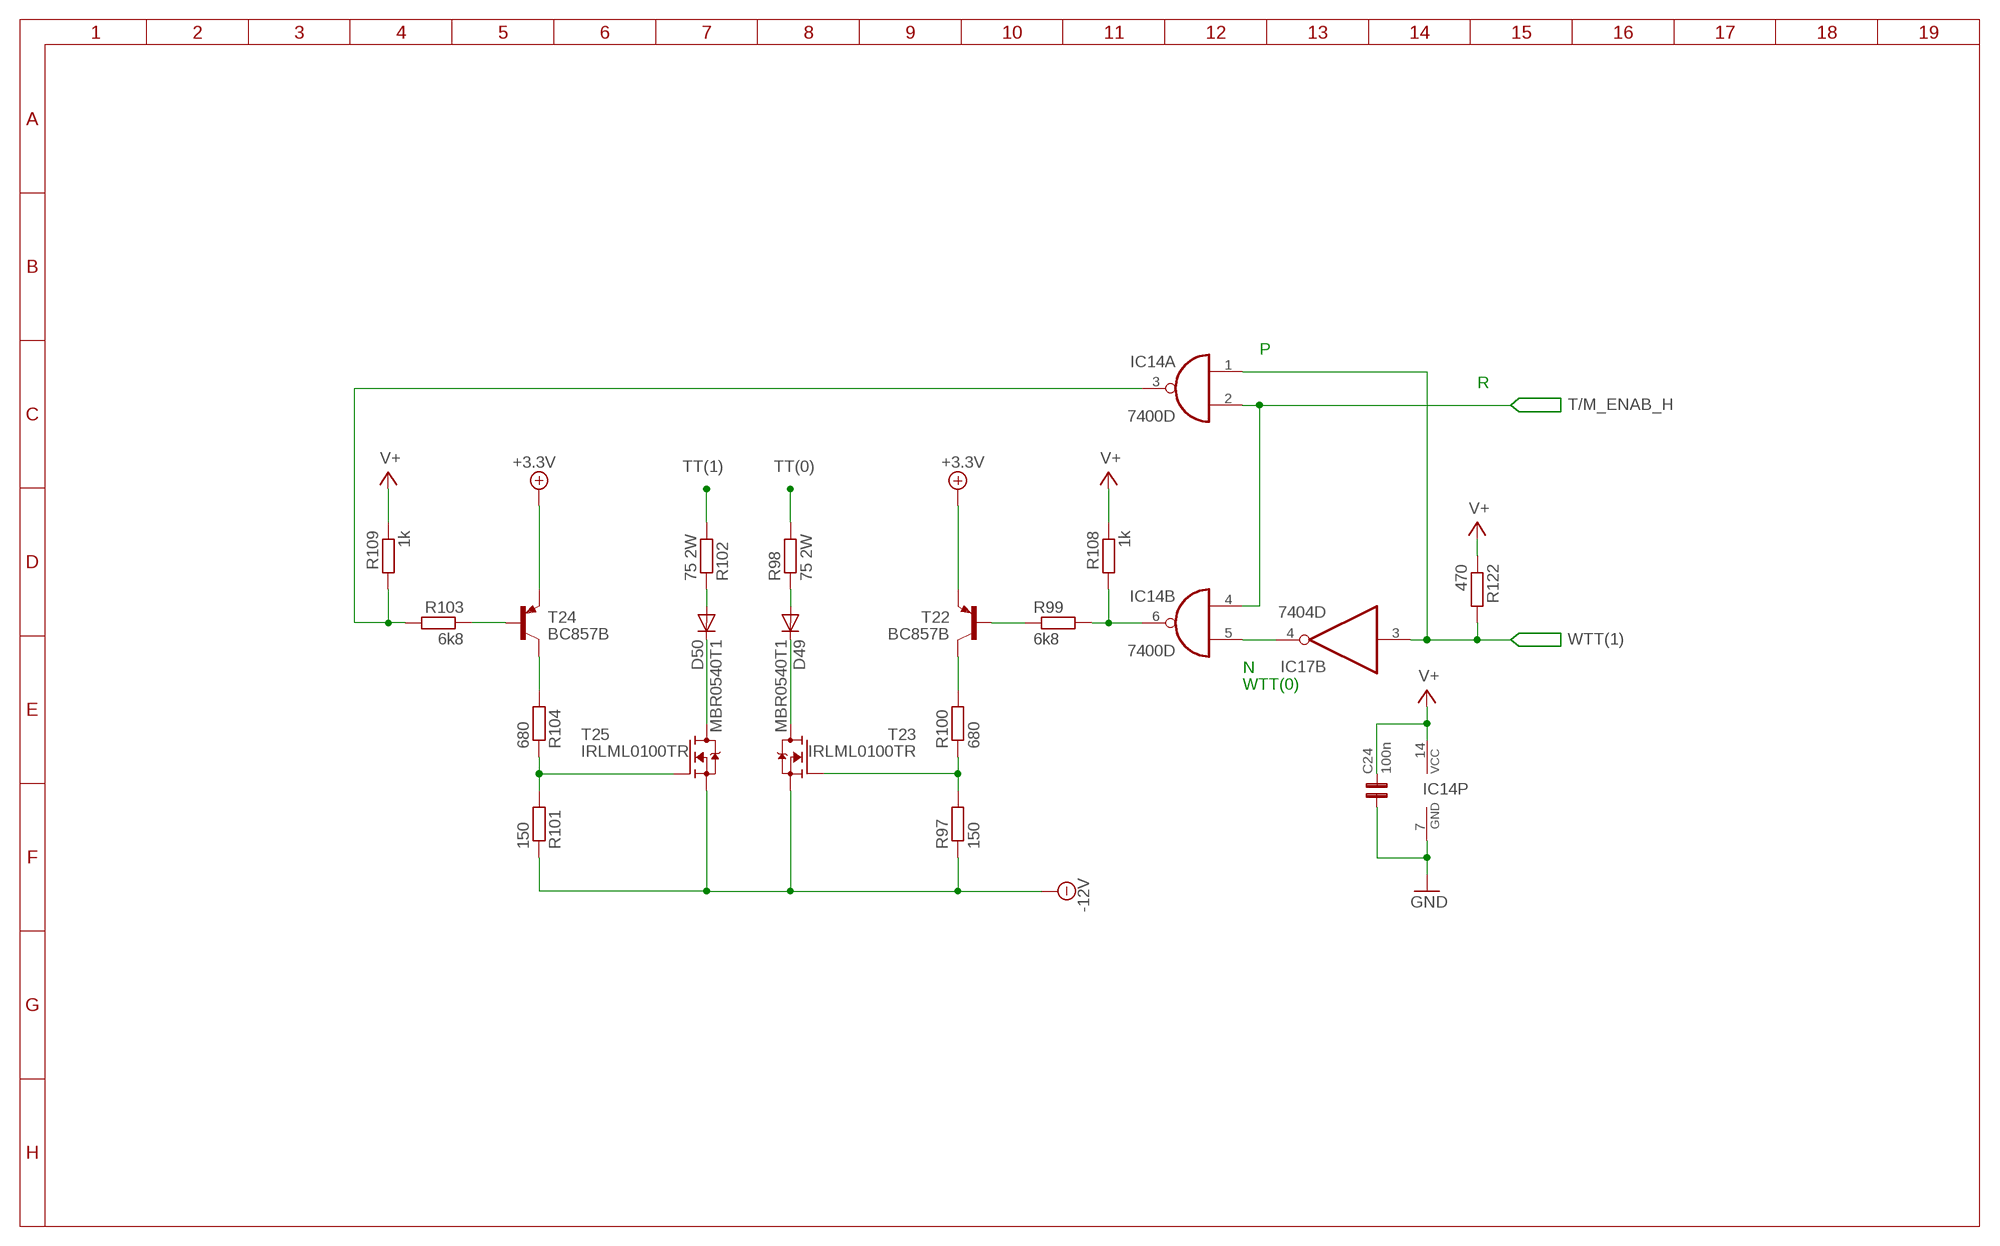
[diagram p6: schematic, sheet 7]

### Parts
C24  100n  C0805  [0805]
D49  MBR0540T1  [SOD123]
D50  MBR0540T1  [SOD123]
IC17  7404D  [SO14]
R97  150  R-EU_R0805  [R0805]
R98  75 2W  R-EU_R2512  [R2512]
R99  6k8  R-EU_R0805  [R0805]
R100  680  R-EU_R0805  [R0805]
R101  150  R-EU_R0805  [R0805]
R102  75 2W  R-EU_R2512  [R2512]
R103  6k8  R-EU_R0805  [R0805]
R104  680  R-EU_R0805  [R0805]
R108  1k  R-EU_R0805  [R0805]
R109  1k  R-EU_R0805  [R0805]
R122  470  R-EU_R0805  [R0805]
T22  BC857B  [SOT23]
T23  IRLML0100TR  [SOT23]
T24  BC857B  [SOT23]
T25  IRLML0100TR  [SOT23]

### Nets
+3.3V: T22.2(E) T24.2(E) ; also sheet 8,9,10,11,13,14
-12V: R97.1 R101.1 T23.2(S) T25.2(S) ; also sheet 8,9,10,11,13,14
GND: C24.1 IC14.7(P:GND) ; also sheet 1,2,3,4,5,6,8,9,10,11,12,13
N$62: IC14.5(B:I1) IC17.4(B:O)
N$81: IC14.6(B:O) R99.2 R108.2
N$83: IC14.3(A:O) R103.2 R109.2
N$131: R99.1 T22.1(B)
N$132: D49.A R98.1
N$135: D49.C T23.3(D)
N$136: R100.2 T22.3(C)
N$139: R97.2 R100.1 T23.1(G)
N$140: R103.1 T24.1(B)
N$143: D50.A R102.1
N$144: D50.C T25.3(D)
N$145: R104.2 T24.3(C)
N$146: R101.2 R104.1 T25.1(G)
T/M_ENAB_H: IC14.2(A:I1) IC14.4(B:I0) ; also sheet 8,12
TT(0): R98.2 ; also sheet 1,2
TT(1): R102.2 ; also sheet 1,2
V+: C24.2 IC14.14(P:VCC) R108.1 R109.1 R122.1 ; also sheet 1,2,3,4,5,6,8,9,10,11,12,13,14
WTT(1): IC14.1(A:I0) IC17.3(B:I) R122.2 ; also sheet 1

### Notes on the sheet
- P
- R
- N
- WTT(0)

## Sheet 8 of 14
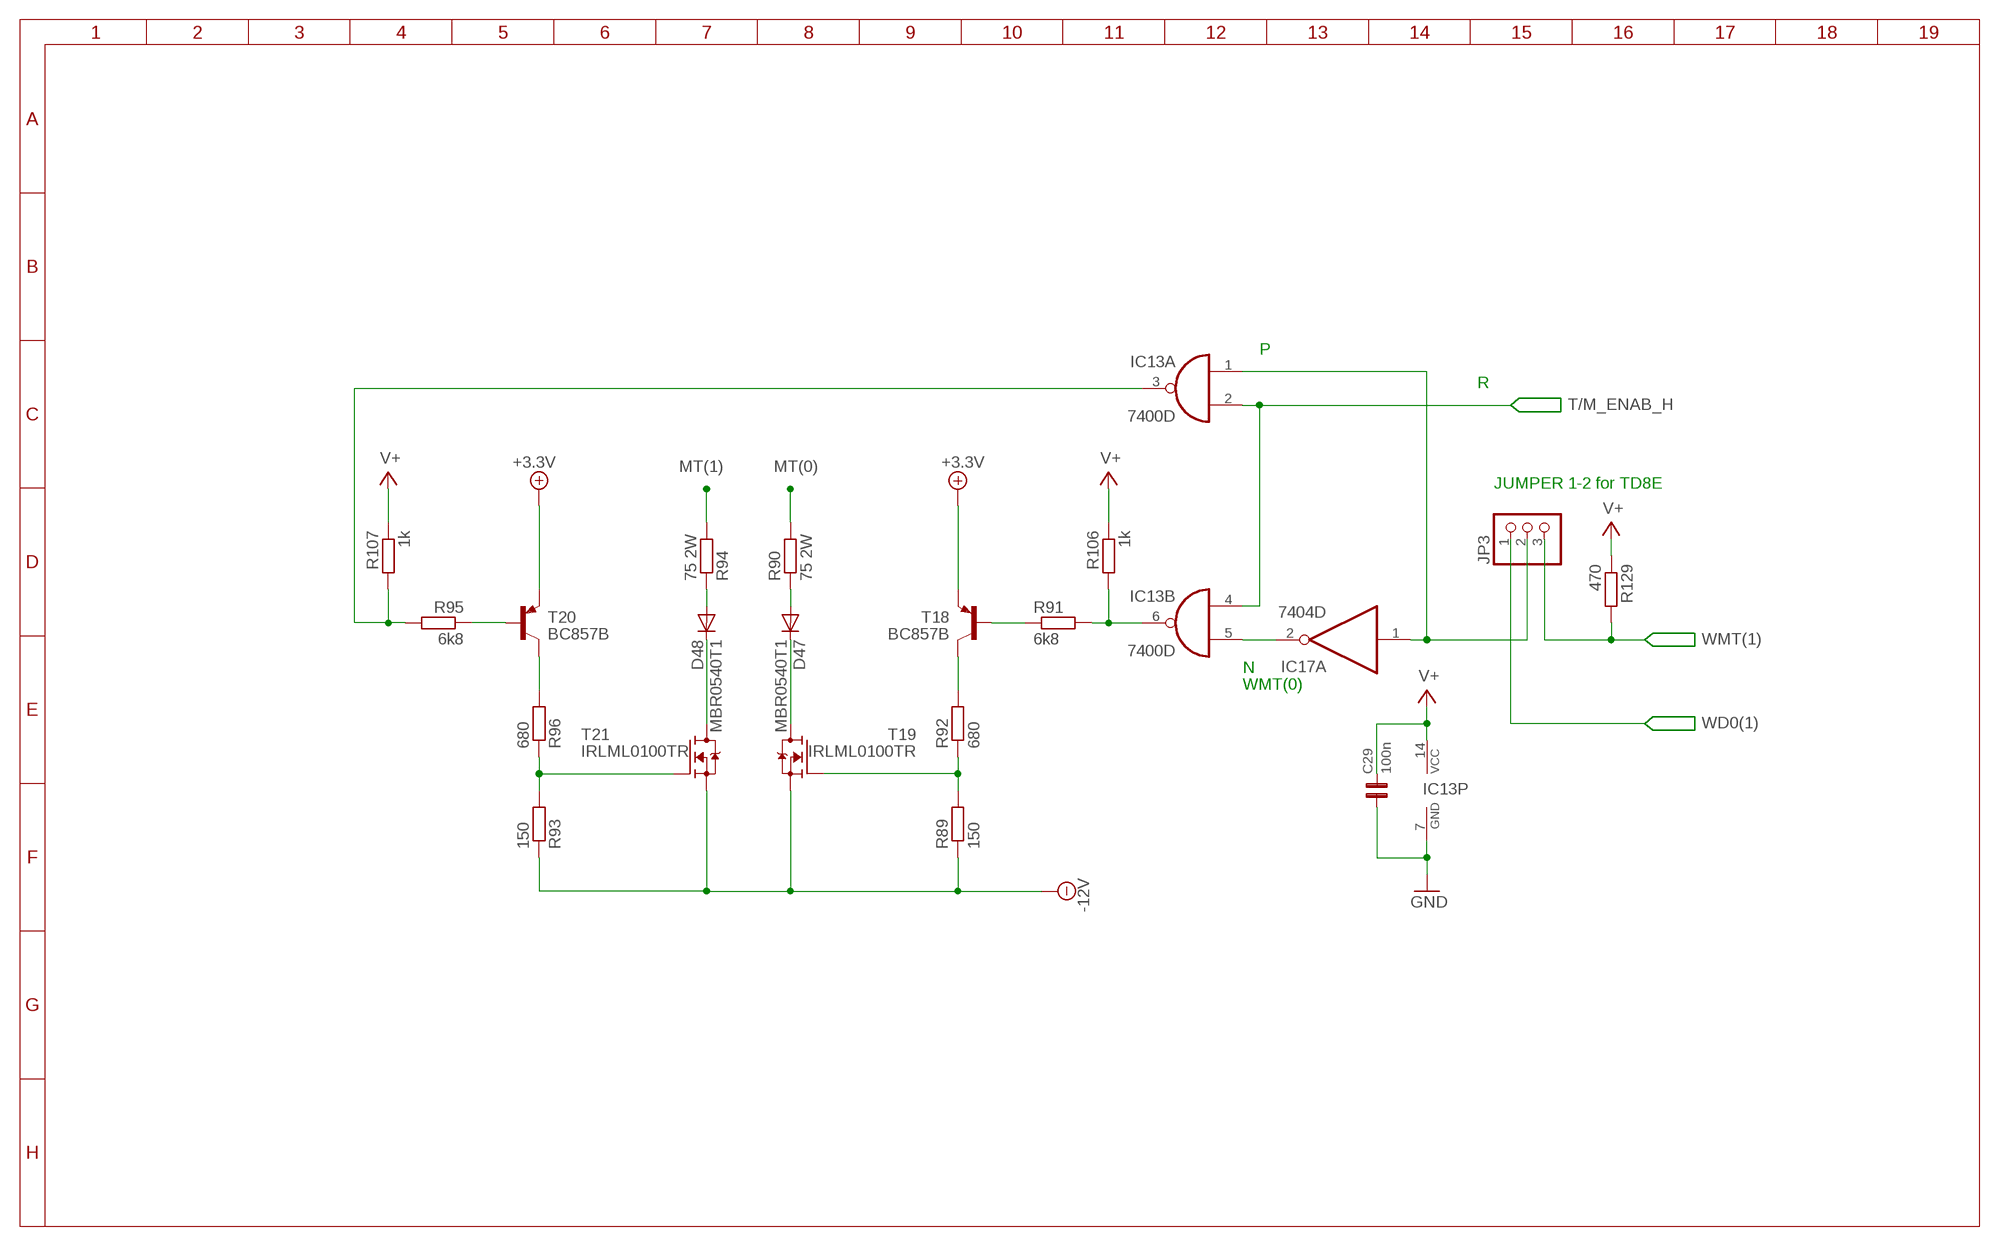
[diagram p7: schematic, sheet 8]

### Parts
C29  100n  C0805  [0805]
D47  MBR0540T1  [SOD123]
D48  MBR0540T1  [SOD123]
JP3  PINHD-1X3  [1X03]
R89  150  R-EU_R0805  [R0805]
R90  75 2W  R-EU_R2512  [R2512]
R91  6k8  R-EU_R0805  [R0805]
R92  680  R-EU_R0805  [R0805]
R93  150  R-EU_R0805  [R0805]
R94  75 2W  R-EU_R2512  [R2512]
R95  6k8  R-EU_R0805  [R0805]
R96  680  R-EU_R0805  [R0805]
R106  1k  R-EU_R0805  [R0805]
R107  1k  R-EU_R0805  [R0805]
R129  470  R-EU_R0805  [R0805]
T18  BC857B  [SOT23]
T19  IRLML0100TR  [SOT23]
T20  BC857B  [SOT23]
T21  IRLML0100TR  [SOT23]

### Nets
+3.3V: T18.2(E) T20.2(E) ; also sheet 7,9,10,11,13,14
-12V: R89.1 R93.1 T19.2(S) T21.2(S) ; also sheet 7,9,10,11,13,14
GND: C29.1 IC13.7(P:GND) ; also sheet 1,2,3,4,5,6,7,9,10,11,12,13
MT(0): R90.2 ; also sheet 1,3
MT(1): R94.2 ; also sheet 1,3
N$78: IC13.6(B:O) R91.2 R106.2
N$80: IC13.3(A:O) R95.2 R107.2
N$104: R91.1 T18.1(B)
N$105: D47.A R90.1
N$107: D47.C T19.3(D)
N$108: R92.2 T18.3(C)
N$109: R89.2 R92.1 T19.1(G)
N$110: R95.1 T20.1(B)
N$111: D48.A R94.1
N$112: D48.C T21.3(D)
N$113: R96.2 T20.3(C)
N$114: R93.2 R96.1 T21.1(G)
N$120: IC13.5(B:I1) IC17.2(A:O)
S_WMT(1): IC13.1(A:I0) IC17.1(A:I) JP3.2
T/M_ENAB_H: IC13.2(A:I1) IC13.4(B:I0) ; also sheet 7,12
V+: C29.2 IC13.14(P:VCC) R106.1 R107.1 R129.1 ; also sheet 1,2,3,4,5,6,7,9,10,11,12,13,14
WD0(1): JP3.1 ; also sheet 1,9
WMT(1): JP3.3 R129.2 ; also sheet 1

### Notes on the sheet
- P
- R
- JUMPER 1-2 for TD8E
- N
- WMT(0)

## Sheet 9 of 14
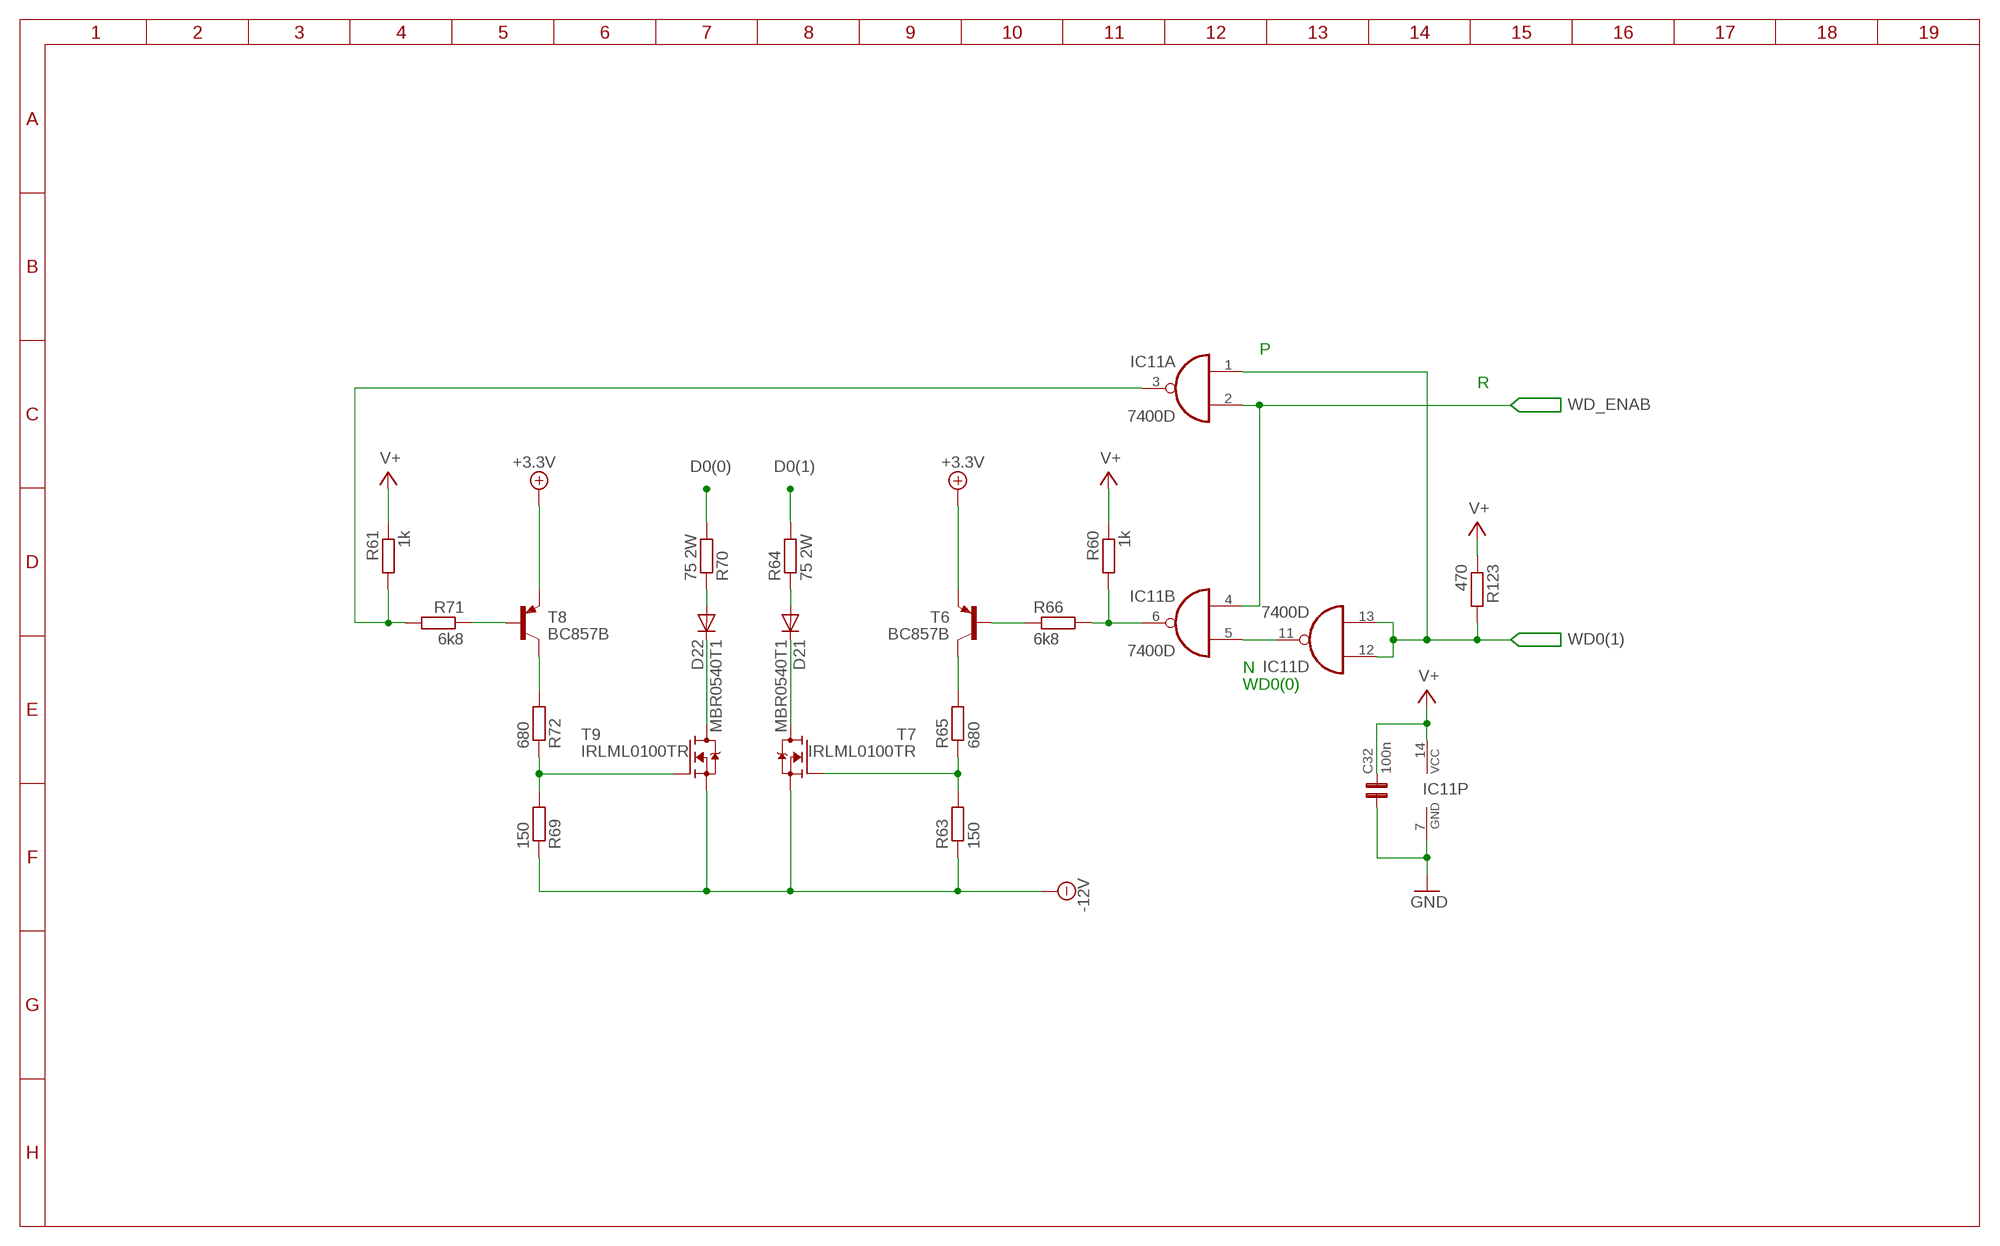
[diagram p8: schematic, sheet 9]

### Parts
C32  100n  C0805  [0805]
D21  MBR0540T1  [SOD123]
D22  MBR0540T1  [SOD123]
R60  1k  R-EU_R0805  [R0805]
R61  1k  R-EU_R0805  [R0805]
R63  150  R-EU_R0805  [R0805]
R64  75 2W  R-EU_R2512  [R2512]
R65  680  R-EU_R0805  [R0805]
R66  6k8  R-EU_R0805  [R0805]
R69  150  R-EU_R0805  [R0805]
R70  75 2W  R-EU_R2512  [R2512]
R71  6k8  R-EU_R0805  [R0805]
R72  680  R-EU_R0805  [R0805]
R123  470  R-EU_R0805  [R0805]
T6  BC857B  [SOT23]
T7  IRLML0100TR  [SOT23]
T8  BC857B  [SOT23]
T9  IRLML0100TR  [SOT23]

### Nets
+3.3V: T6.2(E) T8.2(E) ; also sheet 7,8,10,11,13,14
-12V: R63.1 R69.1 T7.2(S) T9.2(S) ; also sheet 7,8,10,11,13,14
D0(0): R70.2 ; also sheet 1,4
D0(1): R64.2 ; also sheet 1,4
GND: C32.1 IC11.7(P:GND) ; also sheet 1,2,3,4,5,6,7,8,10,11,12,13
N$63: IC11.6(B:O) R60.2 R66.2
N$94: R65.2 T6.3(C)
N$95: R63.2 R65.1 T7.1(G)
N$97: R71.1 T8.1(B)
N$99: R66.1 T6.1(B)
N$100: D22.A R70.1
N$102: D21.A R64.1
N$103: D21.C T7.3(D)
N$125: D22.C T9.3(D)
N$126: R72.2 T8.3(C)
N$127: R69.2 R72.1 T9.1(G)
V+: C32.2 IC11.14(P:VCC) R60.1 R61.1 R123.1 ; also sheet 1,2,3,4,5,6,7,8,10,11,12,13,14
W_DATA1_P: IC11.3(A:O) R61.2 R71.2
WD0(0): IC11.5(B:I1) IC11.11(D:O)
WD0(1): IC11.1(A:I0) IC11.12(D:I0) IC11.13(D:I1) R123.2 ; also sheet 1,8
WD_ENAB: IC11.2(A:I1) IC11.4(B:I0) ; also sheet 10,11,12

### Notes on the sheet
- P
- R
- N
- WD0(0)

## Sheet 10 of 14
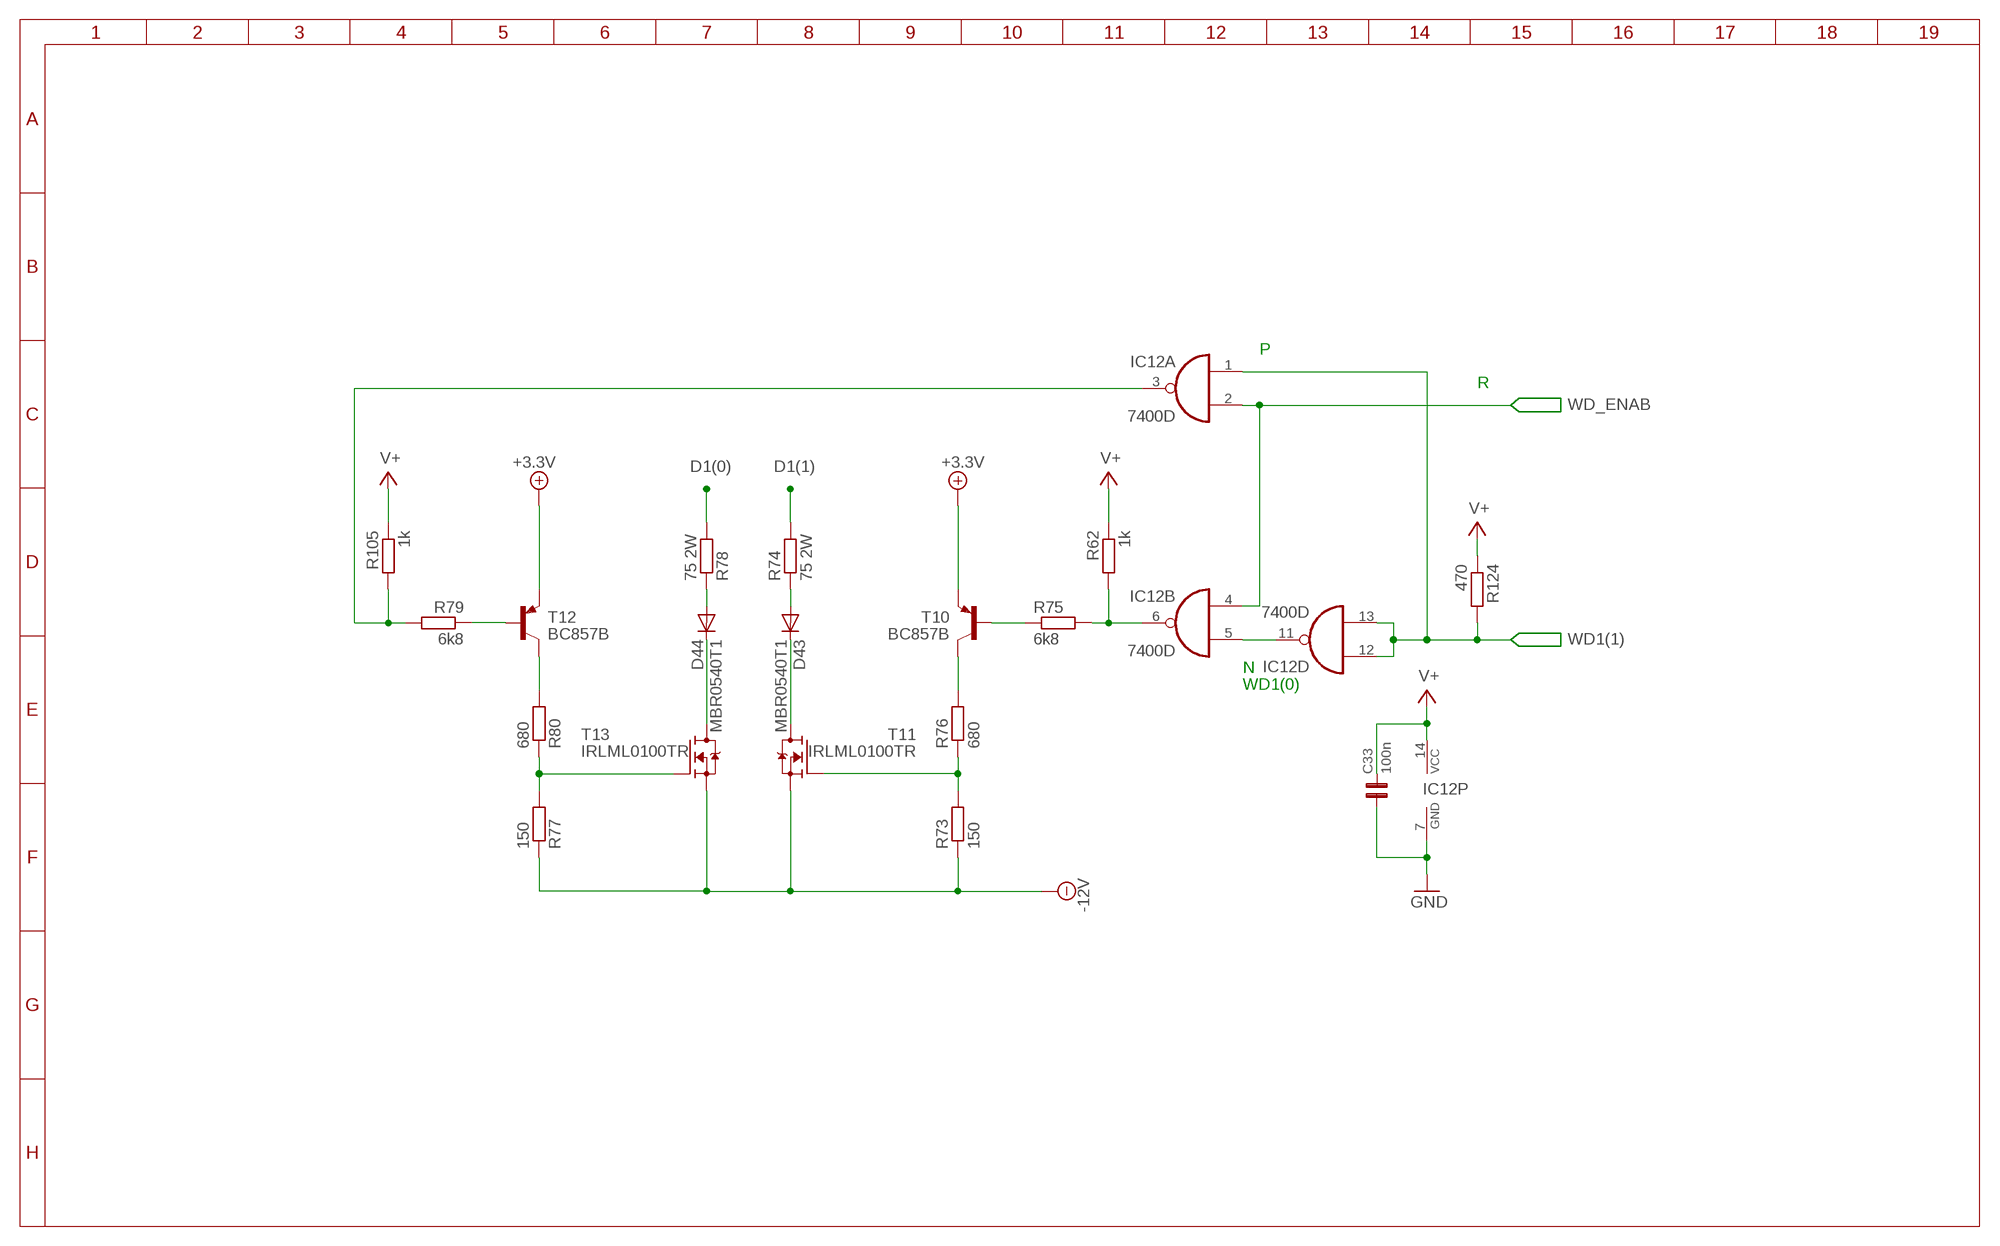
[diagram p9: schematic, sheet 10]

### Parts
C33  100n  C0805  [0805]
D43  MBR0540T1  [SOD123]
D44  MBR0540T1  [SOD123]
R62  1k  R-EU_R0805  [R0805]
R73  150  R-EU_R0805  [R0805]
R74  75 2W  R-EU_R2512  [R2512]
R75  6k8  R-EU_R0805  [R0805]
R76  680  R-EU_R0805  [R0805]
R77  150  R-EU_R0805  [R0805]
R78  75 2W  R-EU_R2512  [R2512]
R79  6k8  R-EU_R0805  [R0805]
R80  680  R-EU_R0805  [R0805]
R105  1k  R-EU_R0805  [R0805]
R124  470  R-EU_R0805  [R0805]
T10  BC857B  [SOT23]
T11  IRLML0100TR  [SOT23]
T12  BC857B  [SOT23]
T13  IRLML0100TR  [SOT23]

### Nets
+3.3V: T10.2(E) T12.2(E) ; also sheet 7,8,9,11,13,14
-12V: R73.1 R77.1 T11.2(S) T13.2(S) ; also sheet 7,8,9,11,13,14
D1(0): R78.2 ; also sheet 1,5
D1(1): R74.2 ; also sheet 1,5
GND: C33.1 IC12.7(P:GND) ; also sheet 1,2,3,4,5,6,7,8,9,11,12,13
N$2: R75.1 T10.1(B)
N$6: D43.A R74.1
N$13: D43.C T11.3(D)
N$15: R76.2 T10.3(C)
N$17: R73.2 R76.1 T11.1(G)
N$18: R79.1 T12.1(B)
N$20: D44.A R78.1
N$21: D44.C T13.3(D)
N$22: R80.2 T12.3(C)
N$23: R77.2 R80.1 T13.1(G)
N$75: IC12.6(B:O) R62.2 R75.2
N$117: IC12.5(B:I1) IC12.11(D:O)
V+: C33.2 IC12.14(P:VCC) R62.1 R105.1 R124.1 ; also sheet 1,2,3,4,5,6,7,8,9,11,12,13,14
W_DATA2_P: IC12.3(A:O) R79.2 R105.2
WD1(1): IC12.1(A:I0) IC12.12(D:I0) IC12.13(D:I1) R124.2 ; also sheet 1
WD_ENAB: IC12.2(A:I1) IC12.4(B:I0) ; also sheet 9,11,12

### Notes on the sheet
- P
- R
- N
- WD1(0)

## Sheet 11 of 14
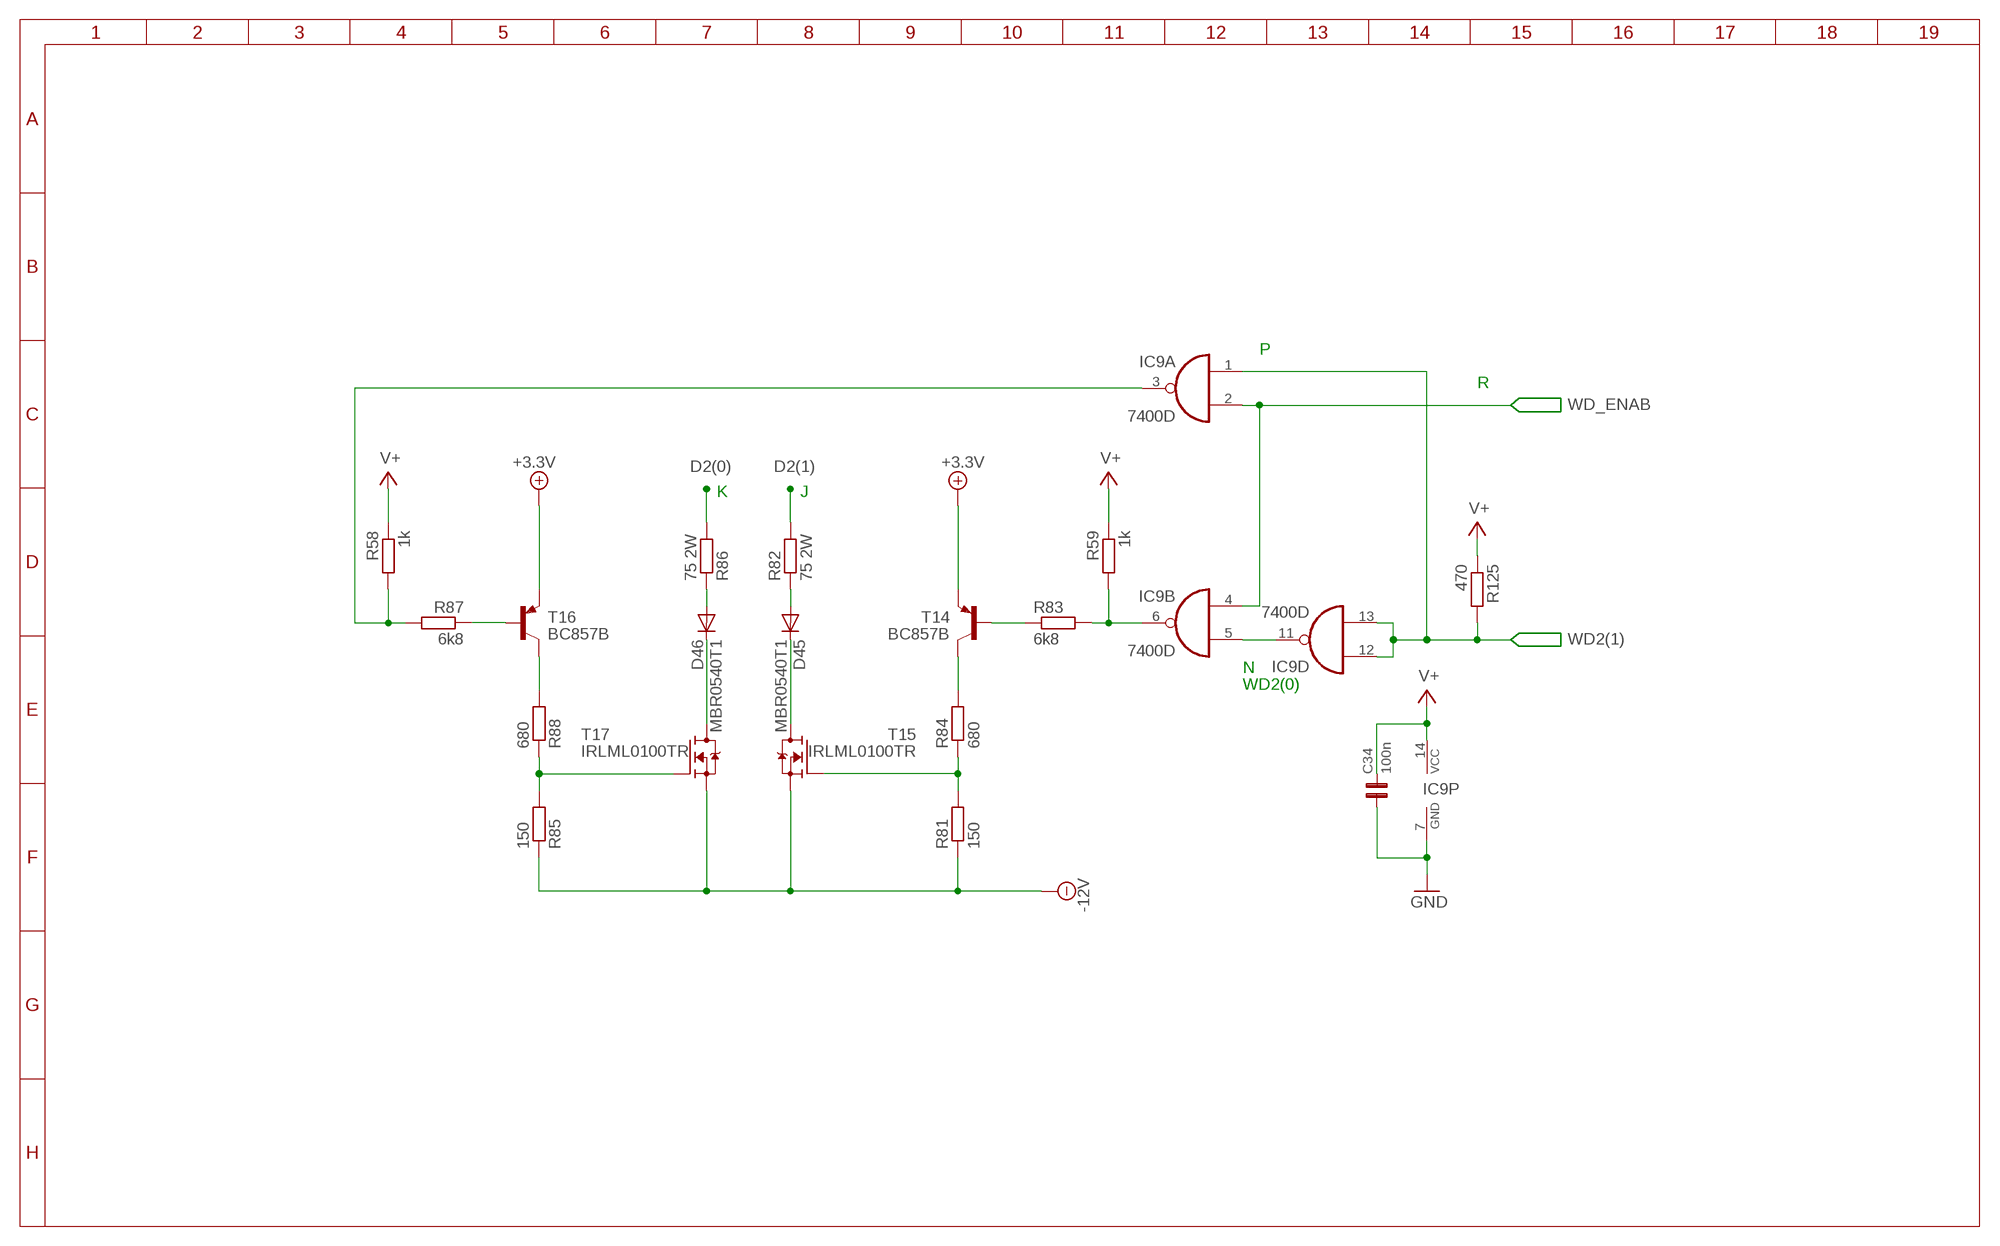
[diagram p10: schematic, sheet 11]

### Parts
C34  100n  C0805  [0805]
D45  MBR0540T1  [SOD123]
D46  MBR0540T1  [SOD123]
R58  1k  R-EU_R0805  [R0805]
R59  1k  R-EU_R0805  [R0805]
R81  150  R-EU_R0805  [R0805]
R82  75 2W  R-EU_R2512  [R2512]
R83  6k8  R-EU_R0805  [R0805]
R84  680  R-EU_R0805  [R0805]
R85  150  R-EU_R0805  [R0805]
R86  75 2W  R-EU_R2512  [R2512]
R87  6k8  R-EU_R0805  [R0805]
R88  680  R-EU_R0805  [R0805]
R125  470  R-EU_R0805  [R0805]
T14  BC857B  [SOT23]
T15  IRLML0100TR  [SOT23]
T16  BC857B  [SOT23]
T17  IRLML0100TR  [SOT23]

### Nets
+3.3V: T14.2(E) T16.2(E) ; also sheet 7,8,9,10,13,14
-12V: R81.1 R85.1 T15.2(S) T17.2(S) ; also sheet 7,8,9,10,13,14
D2(0): R86.2 ; also sheet 1,6
D2(1): R82.2 ; also sheet 1,6
GND: C34.1 IC9.7(P:GND) ; also sheet 1,2,3,4,5,6,7,8,9,10,12,13
N$25: IC9.6(B:O) R59.2 R83.2
N$26: R83.1 T14.1(B)
N$31: D45.A R82.1
N$36: D45.C T15.3(D)
N$39: R84.2 T14.3(C)
N$44: R81.2 R84.1 T15.1(G)
N$50: IC9.5(B:I1) IC9.11(D:O)
N$52: R87.1 T16.1(B)
N$57: D46.A R86.1
N$65: D46.C T17.3(D)
N$70: R88.2 T16.3(C)
N$101: R85.2 R88.1 T17.1(G)
V+: C34.2 IC9.14(P:VCC) R58.1 R59.1 R125.1 ; also sheet 1,2,3,4,5,6,7,8,9,10,12,13,14
W_DATA3_P: IC9.3(A:O) R58.2 R87.2
WD2(1): IC9.1(A:I0) IC9.12(D:I0) IC9.13(D:I1) R125.2 ; also sheet 1
WD_ENAB: IC9.2(A:I1) IC9.4(B:I0) ; also sheet 9,10,12

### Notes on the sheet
- P
- R
- K | J
- N
- WD2(0)

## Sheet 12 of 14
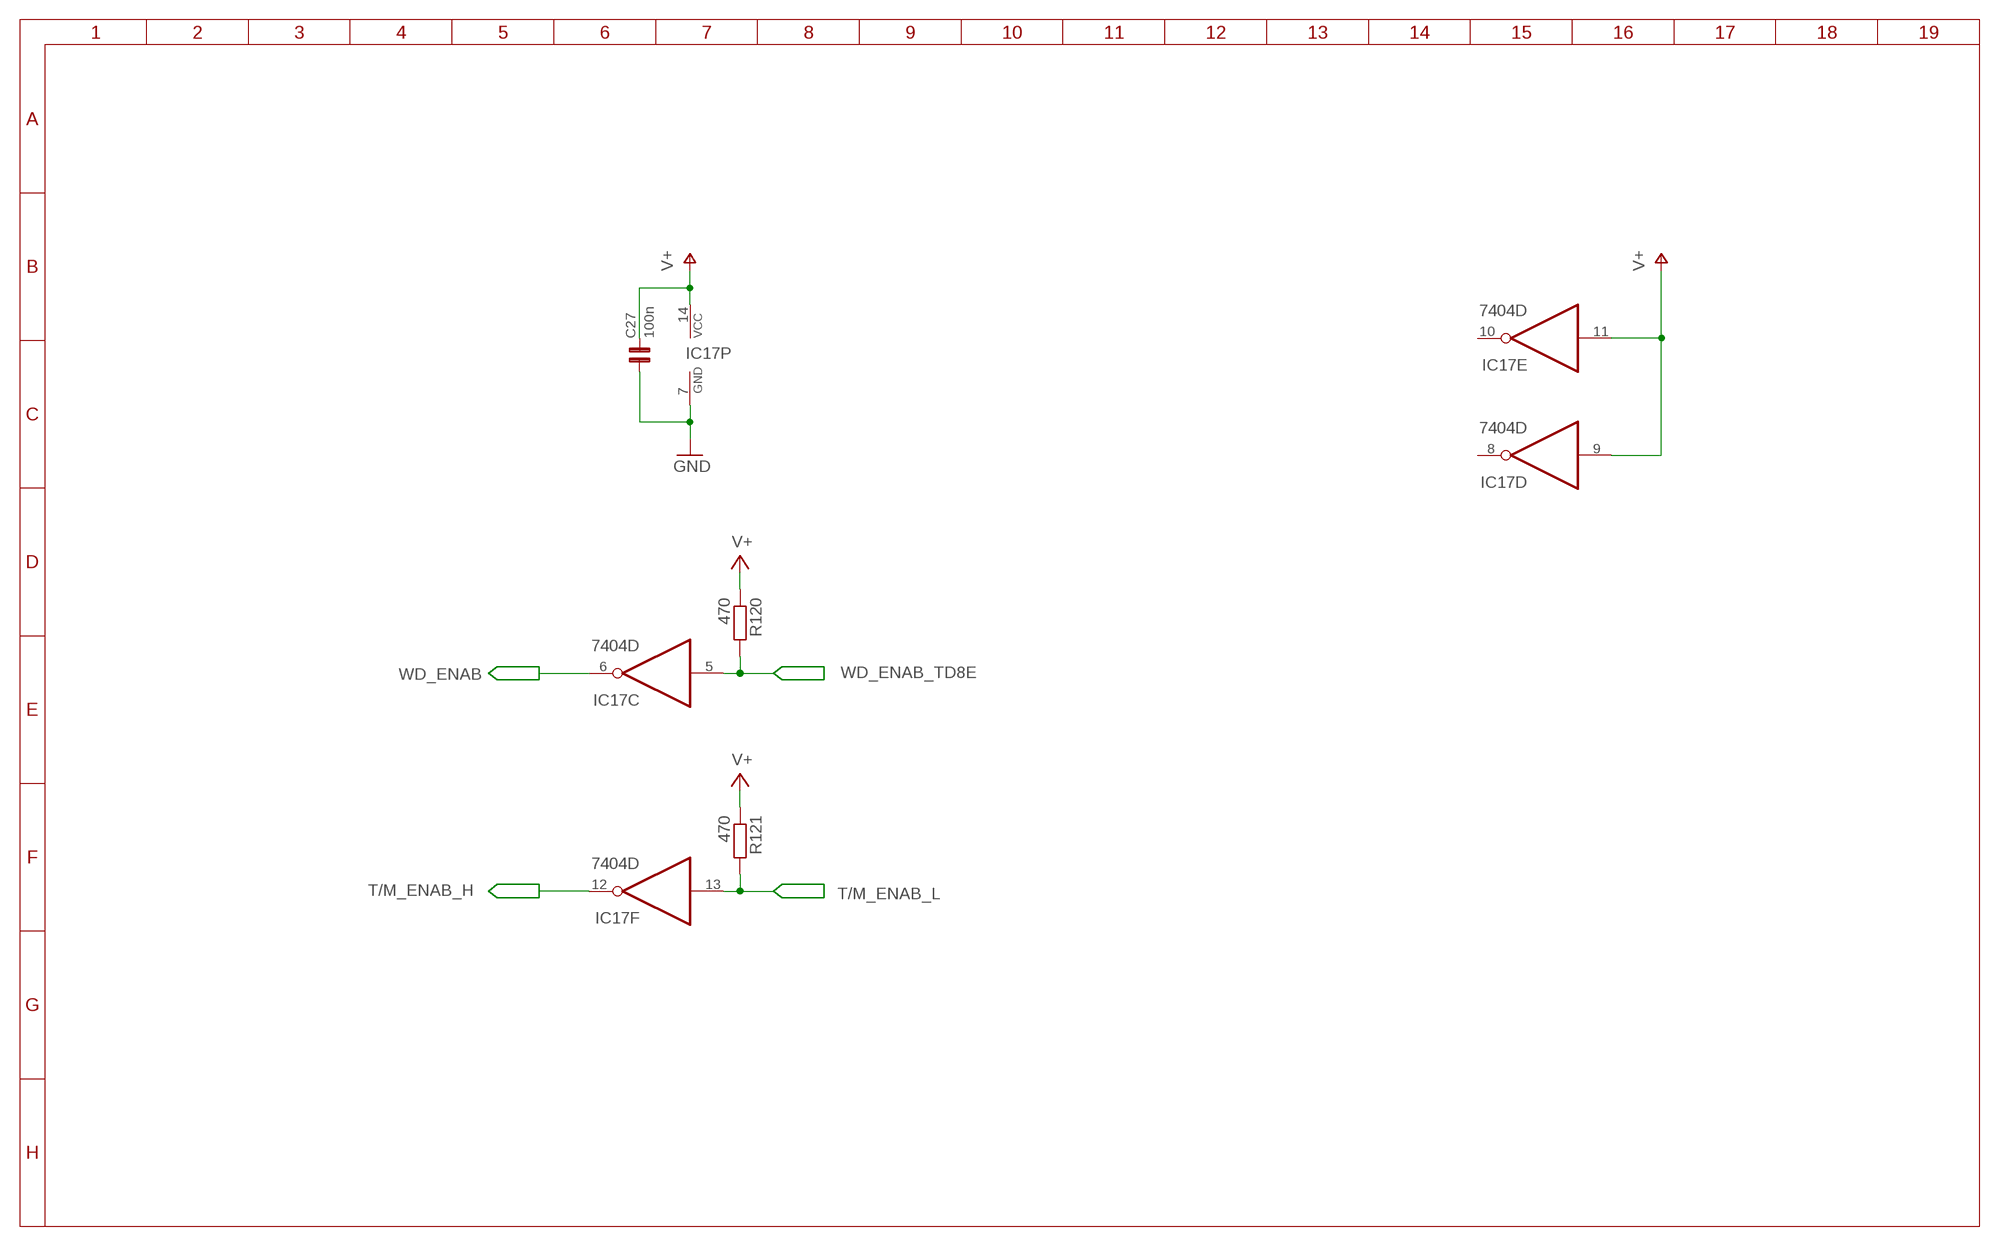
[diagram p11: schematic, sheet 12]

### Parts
C27  100n  C0805  [0805]
R120  470  R-EU_R0805  [R0805]
R121  470  R-EU_R0805  [R0805]

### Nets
GND: C27.1 IC17.7(P:GND) ; also sheet 1,2,3,4,5,6,7,8,9,10,11,13
T/M_ENAB_H: IC17.12(F:O) ; also sheet 7,8
T/M_ENAB_L: IC17.13(F:I) R121.2 ; also sheet 1
V+: C27.2 IC17.9(D:I) IC17.11(E:I) IC17.14(P:VCC) R120.1 R121.1 ; also sheet 1,2,3,4,5,6,7,8,9,10,11,13,14
WD_ENAB: IC17.6(C:O) ; also sheet 9,10,11
WD_ENAB_TD8E: IC17.5(C:I) R120.2 ; also sheet 1
Unconnected: IC17.8(D:O) IC17.10(E:O)

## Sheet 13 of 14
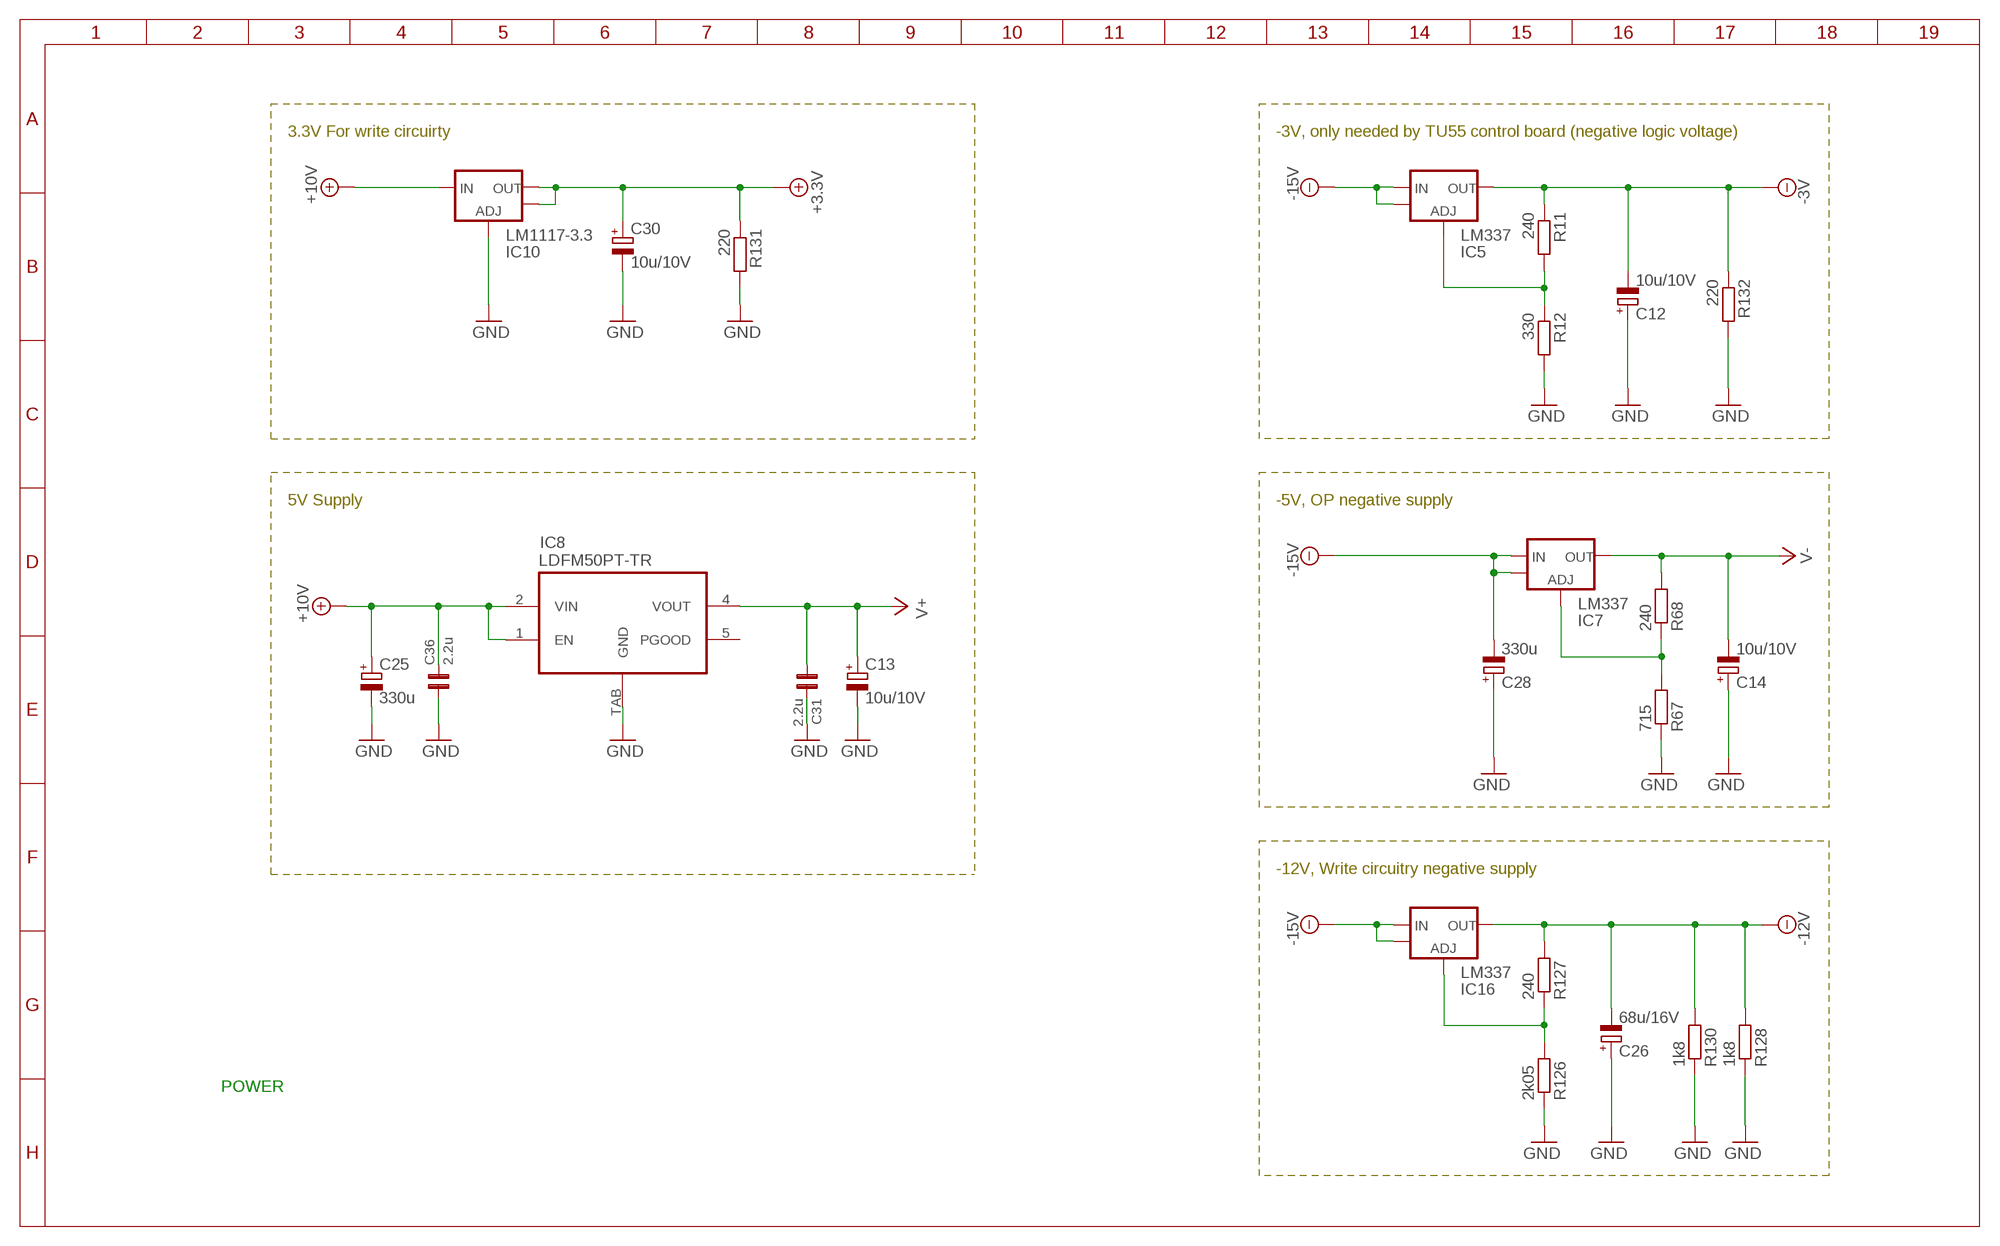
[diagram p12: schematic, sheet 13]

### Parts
C12  10u/10V  CPOL-EUCT3216  [CT3216]
C13  10u/10V  CPOL-EUCT3216  [CT3216]
C14  10u/10V  CPOL-EUCT3216  [CT3216]
C25  330u  CPOL-EUE22-9AXIAL  [E22-9]
C26  68u/16V  CPOL-EUCT6032  [CT6032]
C28  330u  CPOL-EUE22-9AXIAL  [E22-9]
C30  10u/10V  CPOL-EUCT3216  [CT3216]
C31  2.2u  C0805  [0805]
C36  2.2u  C0805  [0805]
IC5  LM337  LM337-SOT223  [SOT223]
IC7  LM337  LM337-SOT223  [SOT223]
IC8  LDFM50PT-TR  [PPAK]
IC10  LM1117-3.3  [SOT223]
IC16  LM337  LM337-SOT223  [SOT223]
R11  240  R-EU_R0805  [R0805]
R12  330  R-EU_R0805  [R0805]
R67  715  R-EU_R0805  [R0805]
R68  240  R-EU_R0805  [R0805]
R126  2k05  R-EU_R0805  [R0805]
R127  240  R-EU_R0805  [R0805]
R128  1k8  R-EU_R0805  [R0805]
R130  1k8  R-EU_R0805  [R0805]
R131  220  R-EU_R0805  [R0805]
R132  220  R-EU_R0805  [R0805]

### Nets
+3.3V: C30.+ IC10.2(OUT) IC10.4(OUT_TAB) R131.1 ; also sheet 7,8,9,10,11,14
+10V: C25.+ C36.2 IC8.1(EN) IC8.2(VIN) IC10.3(IN) ; also sheet 1
-3V: C12.- IC5.3(OUT) R11.1 R132.1 ; also sheet 1,14
-12V: C26.- IC16.3(OUT) R127.2 R128.2 R130.2 ; also sheet 7,8,9,10,11,14
-15V: C28.- IC5.2(IN) IC5.4(IN_TAB) IC7.2(IN) IC7.4(IN_TAB) IC16.2(IN) IC16.4(IN_TAB) ; also sheet 1
GND: C12.+ C13.- C14.+ C25.- C26.+ C28.+ C30.- C31.2 C36.1 IC8.TAB(GND) IC10.1(GND) R12.2 R67.1 R126.1 R128.1 R130.1 R131.2 R132.2 ; also sheet 1,2,3,4,5,6,7,8,9,10,11,12
N$24: IC5.1(ADJ) R11.2 R12.1
N$96: IC7.1(ADJ) R67.2 R68.1
N$119: IC16.1(ADJ) R126.2 R127.1
V+: C13.+ C31.1 IC8.4(VOUT) ; also sheet 1,2,3,4,5,6,7,8,9,10,11,12,14
V-: C14.- IC7.3(OUT) R68.2 ; also sheet 2,3,4,5,6,14
Unconnected: IC8.5(PGOOD)

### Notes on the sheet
- 3.3V For write circuirty | -3V, only needed by TU55 control board (negative logic voltage)
- 5V Supply | -5V, OP negative supply
- -12V, Write circuitry negative supply
- POWER

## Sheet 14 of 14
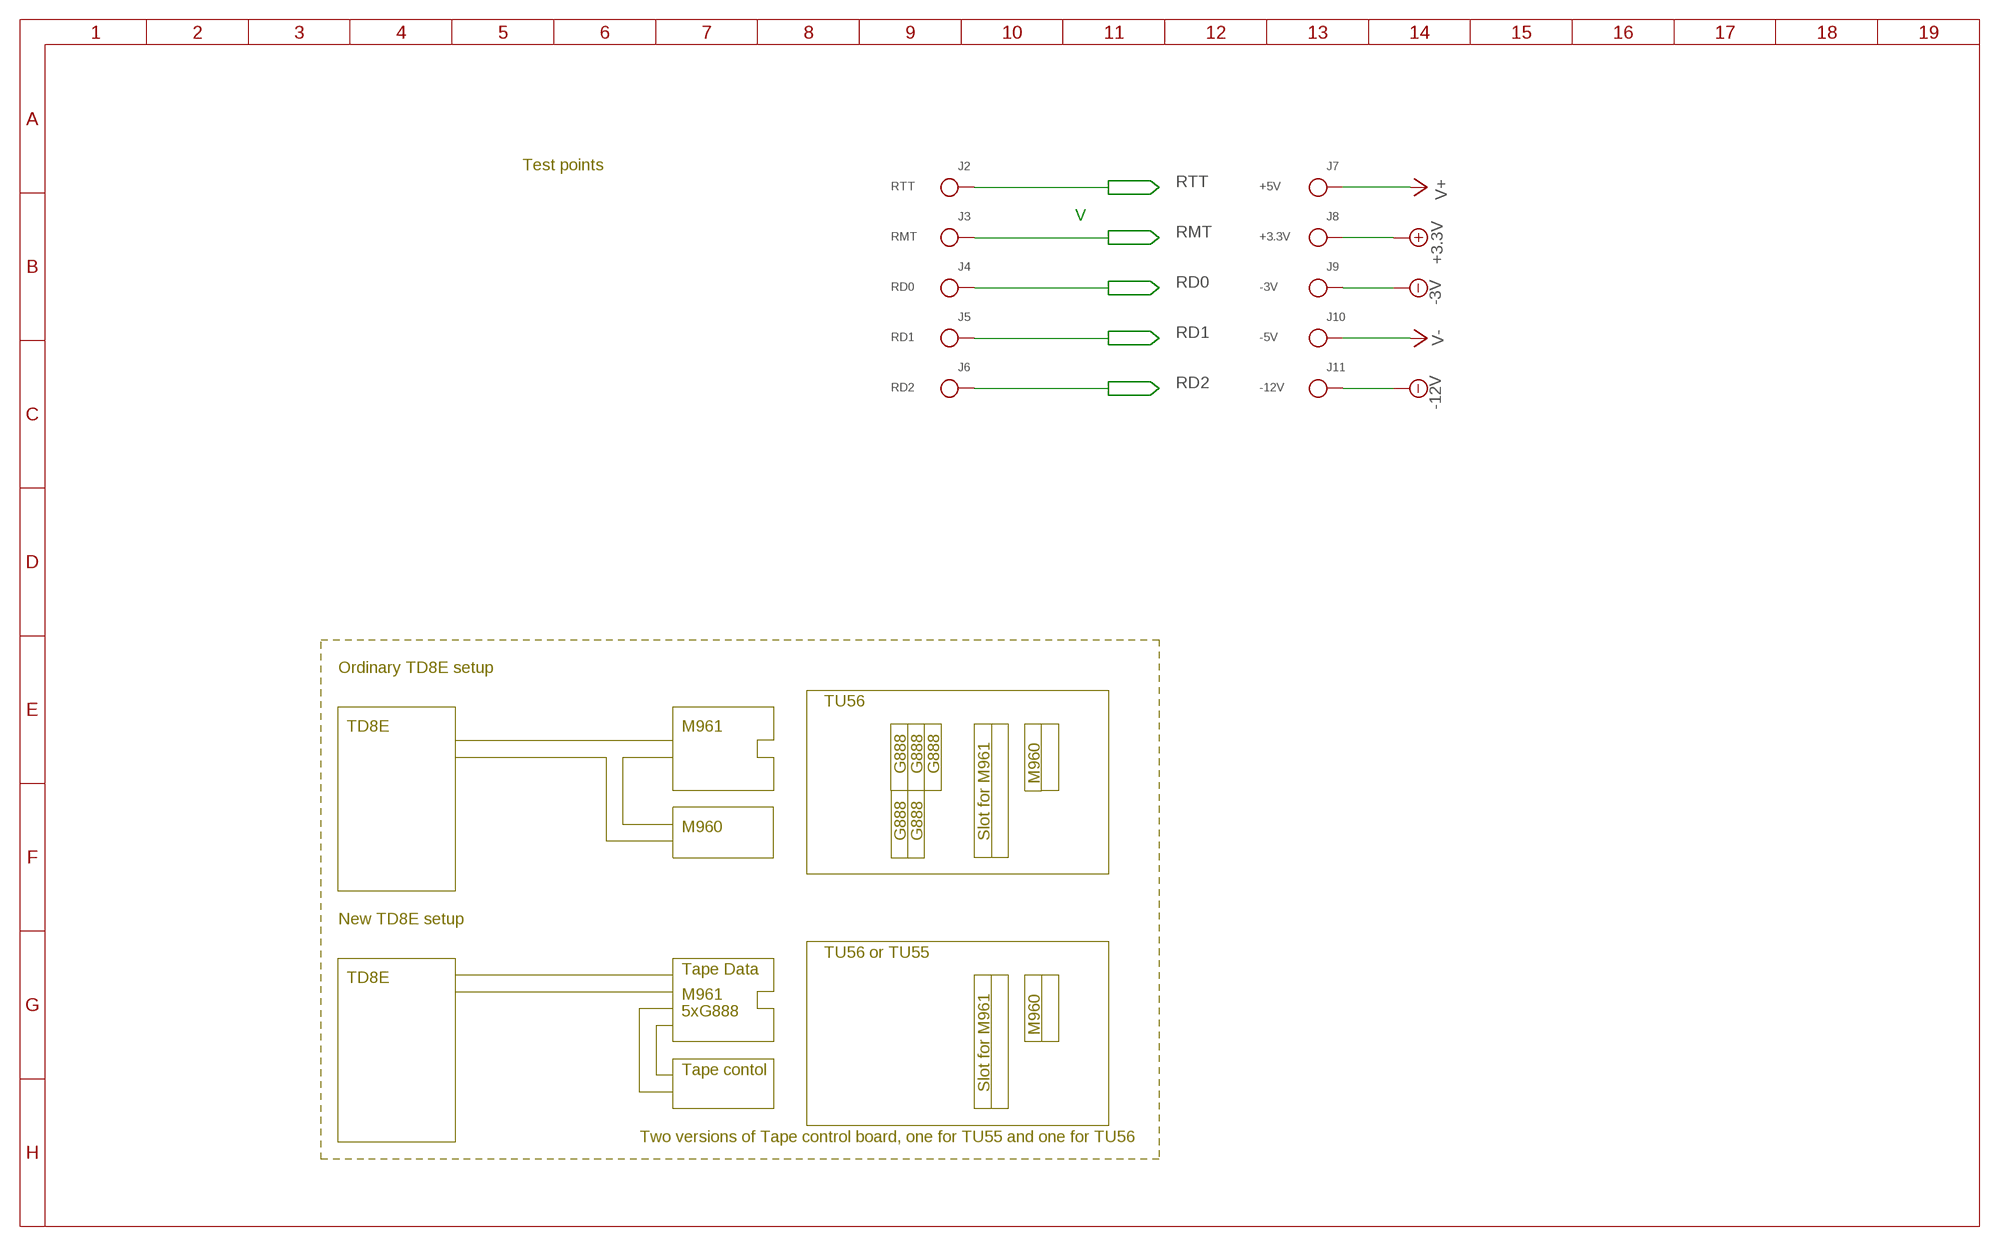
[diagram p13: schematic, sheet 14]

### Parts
J2  RTT  SOLDER_PINTP2  [TESTPOINT-2]
J3  RMT  SOLDER_PINTP2  [TESTPOINT-2]
J4  RD0  SOLDER_PINTP2  [TESTPOINT-2]
J5  RD1  SOLDER_PINTP2  [TESTPOINT-2]
J6  RD2  SOLDER_PINTP2  [TESTPOINT-2]
J7  +5V  SOLDER_PINTP2  [TESTPOINT-2]
J8  +3.3V  SOLDER_PINTP2  [TESTPOINT-2]
J9  -3V  SOLDER_PINTP2  [TESTPOINT-2]
J10  -5V  SOLDER_PINTP2  [TESTPOINT-2]
J11  -12V  SOLDER_PINTP2  [TESTPOINT-2]

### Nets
+3.3V: J8.P$1 ; also sheet 7,8,9,10,11,13
-3V: J9.P$1 ; also sheet 1,13
-12V: J11.P$1 ; also sheet 7,8,9,10,11,13
RD0: J4.P$1 ; also sheet 1,4
RD1: J5.P$1 ; also sheet 1,5
RD2: J6.P$1 ; also sheet 1,6
RMT: J3.P$1 ; also sheet 1,3
RTT: J2.P$1 ; also sheet 1,2
V+: J7.P$1 ; also sheet 1,2,3,4,5,6,7,8,9,10,11,12,13
V-: J10.P$1 ; also sheet 2,3,4,5,6,13

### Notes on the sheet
- Test points
- V
- Ordinary TD8E setup
- TU56
- TD8E | M961
- G888 | G888 | G888
- M960
- M960
- G888 | G888 | Slot for M961
- New TD8E setup
- TU56 or TU55
- Tape Data
- TD8E
- M961
- 5xG888
- M960
- Tape contol
- Slot for M961
- Two versions of Tape control board, one for TU55 and one for TU56

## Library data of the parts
C1-C11 C15-C24 C27 C29 C31-C34 C36 = capsmd:C0805
C12-C14 C25 C26 C28 C30 = anders:CPOL-EU: POLARIZED CAPACITOR, European symbol
D1-D20 D23-D42 D51-D65 = diode:1N4148: DIODE
D21 D22 D43-D50 = anders:MBR0540T1: Schottky diod 0,5A
IC1-IC4 IC6 = linear:OPA2134: SoundPLUS (TM) High Performance AUDIO OPERATIONAL AMPLIFIERS Source: http://focus.ti.com/lit/ds/sbos058/sbos058.pdf
IC5 IC7 IC16 = v-reg:LM337-SOT223: LM337 surface mount
IC8 = anders:LDFM50PT-TR
IC9 IC11-IC14 = 74xx-eu:74*00: Quad 2-input NAND gate
IC10 = v-reg:LM1117
IC17 = 74xx-eu:74*04: Hex INVERTER
J1 = anders:FLIPCHIP_2-SBS
J2-J11 = anders:SOLDER_PIN
JP1 = pinhead:PINHD-2X10: PIN HEADER
JP2 = pinhead:PINHD-2X20: PIN HEADER
JP3 = pinhead:PINHD-1X3: PIN HEADER
R1-R26 R28-R109 R111 R112 R114 R115 R117 R118 R120-R137 = anders:R-EU_: RESISTOR, European symbol
R27 R110 R113 R116 R119 = anders:TRIM_EU-: POTENTIOMETER
T1-T5 = transistor:BC847: NPN TRANSISTOR
T6 T8 T10 T12 T14 T16 T18 T20 T22 T24 = anders:BC857B: PNP Transistor
T7 T9 T11 T13 T15 T17 T19 T21 T23 T25 = anders:IRLML0100TR: N-channel MOSFET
